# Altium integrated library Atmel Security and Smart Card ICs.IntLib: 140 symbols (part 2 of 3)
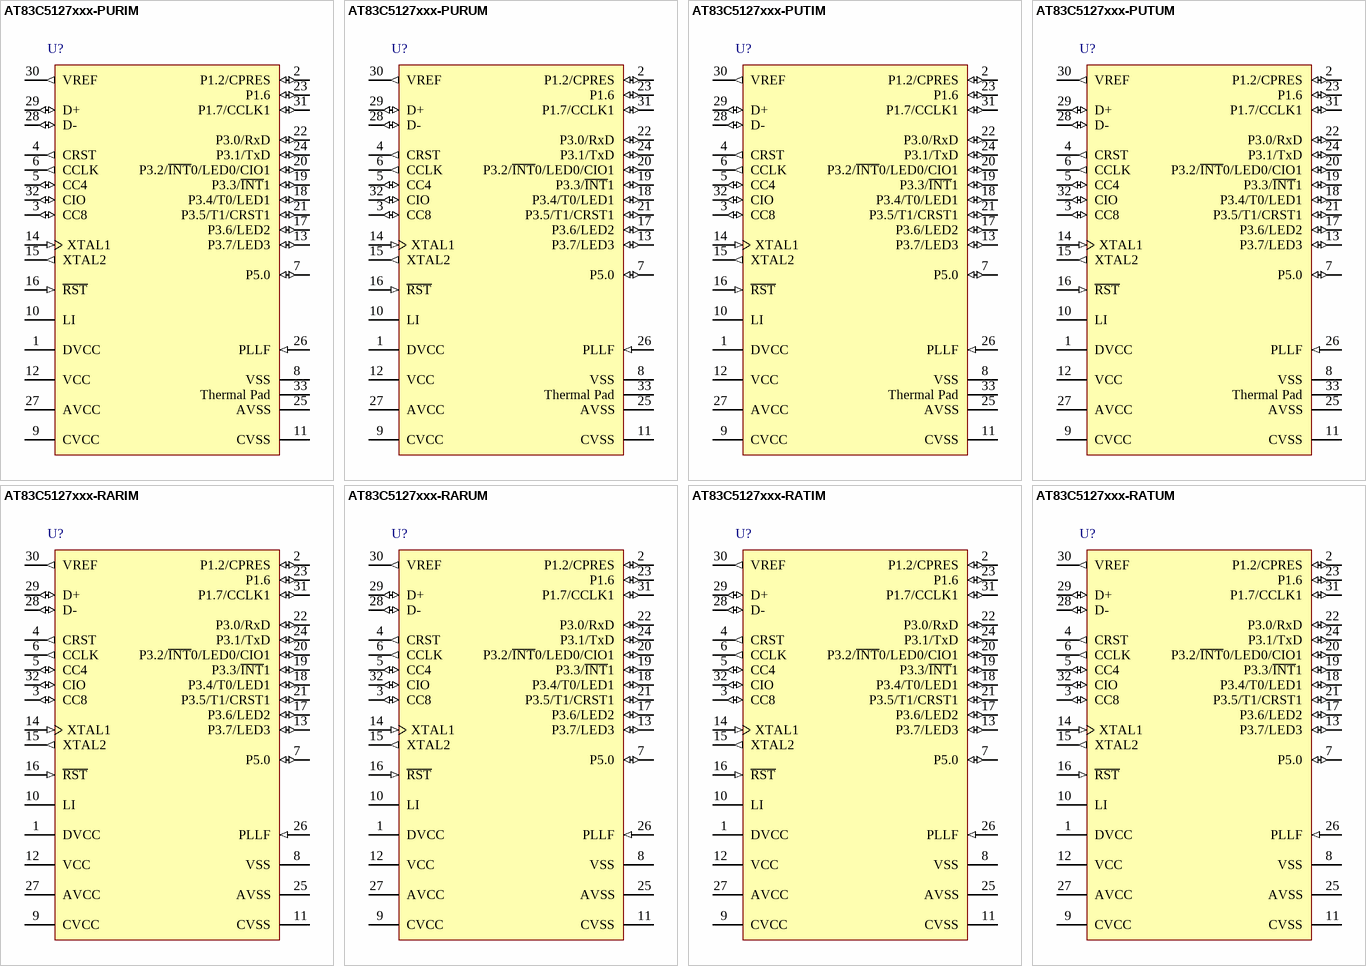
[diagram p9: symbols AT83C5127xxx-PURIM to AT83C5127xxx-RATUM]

## AT83C5127xxx-RARIM
designator U?
C51 Microcontroller with USB and Smart Card Reader Interfaces, Industrial, 32-Pin QFP Pkg, Tape and Reel
footprint LQFP32_N (Thin QFP, 32-Leads, Body 7x7mm, Pitch 0.8mm, IPC Medium Density)
footprint LQFP32_L (Thin QFP, 32-Leads, Body 7x7mm, Pitch 0.8mm, IPC High Density)
footprint LQFP32_M (Thin QFP, 32-Leads, Body 7x7mm, Pitch 0.8mm, IPC Low Density)
pins: 1 DVCC (power), 2 P1.2/CPRES (io), 3 CC8 (io), 4 CRST (out), 5 CC4 (io), 6 CCLK (out), 7 P5.0 (io), 8 VSS (power), 9 CVCC (power), 10 LI (power), 11 CVSS (power), 12 VCC (power), 13 P3.7/LED3 (io), 14 XTAL1 (in), 15 XTAL2 (out), 16 ~{RST} (in), 17 P3.6/LED2 (io), 18 P3.4/T0/LED1 (io), 19 P3.3/~{INT}1 (io), 20 P3.2/~{INT}0/LED0/CIO1 (io), 21 P3.5/T1/CRST1 (io), 22 P3.0/RxD (io), 23 P1.6 (io), 24 P3.1/TxD (io), 25 AVSS (power), 26 PLLF (in), 27 AVCC (power), 28 D- (io), 29 D+ (io), 30 VREF (out), 31 P1.7/CCLK1 (io), 32 CIO (io)

## AT83C5127xxx-RARUM
designator U?
C51 Microcontroller with USB and Smart Card Reader Interfaces, Industrial, 32-Pin QFP Pkg, Tape and Reel, Pb-Free
footprint LQFP32_N (Thin QFP, 32-Leads, Body 7x7mm, Pitch 0.8mm, IPC Medium Density)
footprint LQFP32_L (Thin QFP, 32-Leads, Body 7x7mm, Pitch 0.8mm, IPC High Density)
footprint LQFP32_M (Thin QFP, 32-Leads, Body 7x7mm, Pitch 0.8mm, IPC Low Density)
pins: 1 DVCC (power), 2 P1.2/CPRES (io), 3 CC8 (io), 4 CRST (out), 5 CC4 (io), 6 CCLK (out), 7 P5.0 (io), 8 VSS (power), 9 CVCC (power), 10 LI (power), 11 CVSS (power), 12 VCC (power), 13 P3.7/LED3 (io), 14 XTAL1 (in), 15 XTAL2 (out), 16 ~{RST} (in), 17 P3.6/LED2 (io), 18 P3.4/T0/LED1 (io), 19 P3.3/~{INT}1 (io), 20 P3.2/~{INT}0/LED0/CIO1 (io), 21 P3.5/T1/CRST1 (io), 22 P3.0/RxD (io), 23 P1.6 (io), 24 P3.1/TxD (io), 25 AVSS (power), 26 PLLF (in), 27 AVCC (power), 28 D- (io), 29 D+ (io), 30 VREF (out), 31 P1.7/CCLK1 (io), 32 CIO (io)

## AT83C5127xxx-RATIM
designator U?
C51 Microcontroller with USB and Smart Card Reader Interfaces, Industrial, 32-Pin QFP Pkg, Tray
footprint LQFP32_N (Thin QFP, 32-Leads, Body 7x7mm, Pitch 0.8mm, IPC Medium Density)
footprint LQFP32_L (Thin QFP, 32-Leads, Body 7x7mm, Pitch 0.8mm, IPC High Density)
footprint LQFP32_M (Thin QFP, 32-Leads, Body 7x7mm, Pitch 0.8mm, IPC Low Density)
pins: 1 DVCC (power), 2 P1.2/CPRES (io), 3 CC8 (io), 4 CRST (out), 5 CC4 (io), 6 CCLK (out), 7 P5.0 (io), 8 VSS (power), 9 CVCC (power), 10 LI (power), 11 CVSS (power), 12 VCC (power), 13 P3.7/LED3 (io), 14 XTAL1 (in), 15 XTAL2 (out), 16 ~{RST} (in), 17 P3.6/LED2 (io), 18 P3.4/T0/LED1 (io), 19 P3.3/~{INT}1 (io), 20 P3.2/~{INT}0/LED0/CIO1 (io), 21 P3.5/T1/CRST1 (io), 22 P3.0/RxD (io), 23 P1.6 (io), 24 P3.1/TxD (io), 25 AVSS (power), 26 PLLF (in), 27 AVCC (power), 28 D- (io), 29 D+ (io), 30 VREF (out), 31 P1.7/CCLK1 (io), 32 CIO (io)

## AT83C5127xxx-RATUM
designator U?
C51 Microcontroller with USB and Smart Card Reader Interfaces, Industrial, 32-Pin QFP Pkg, Tray, Pb-Free
footprint LQFP32_N (Thin QFP, 32-Leads, Body 7x7mm, Pitch 0.8mm, IPC Medium Density)
footprint LQFP32_L (Thin QFP, 32-Leads, Body 7x7mm, Pitch 0.8mm, IPC High Density)
footprint LQFP32_M (Thin QFP, 32-Leads, Body 7x7mm, Pitch 0.8mm, IPC Low Density)
pins: 1 DVCC (power), 2 P1.2/CPRES (io), 3 CC8 (io), 4 CRST (out), 5 CC4 (io), 6 CCLK (out), 7 P5.0 (io), 8 VSS (power), 9 CVCC (power), 10 LI (power), 11 CVSS (power), 12 VCC (power), 13 P3.7/LED3 (io), 14 XTAL1 (in), 15 XTAL2 (out), 16 ~{RST} (in), 17 P3.6/LED2 (io), 18 P3.4/T0/LED1 (io), 19 P3.3/~{INT}1 (io), 20 P3.2/~{INT}0/LED0/CIO1 (io), 21 P3.5/T1/CRST1 (io), 22 P3.0/RxD (io), 23 P1.6 (io), 24 P3.1/TxD (io), 25 AVSS (power), 26 PLLF (in), 27 AVCC (power), 28 D- (io), 29 D+ (io), 30 VREF (out), 31 P1.7/CCLK1 (io), 32 CIO (io)

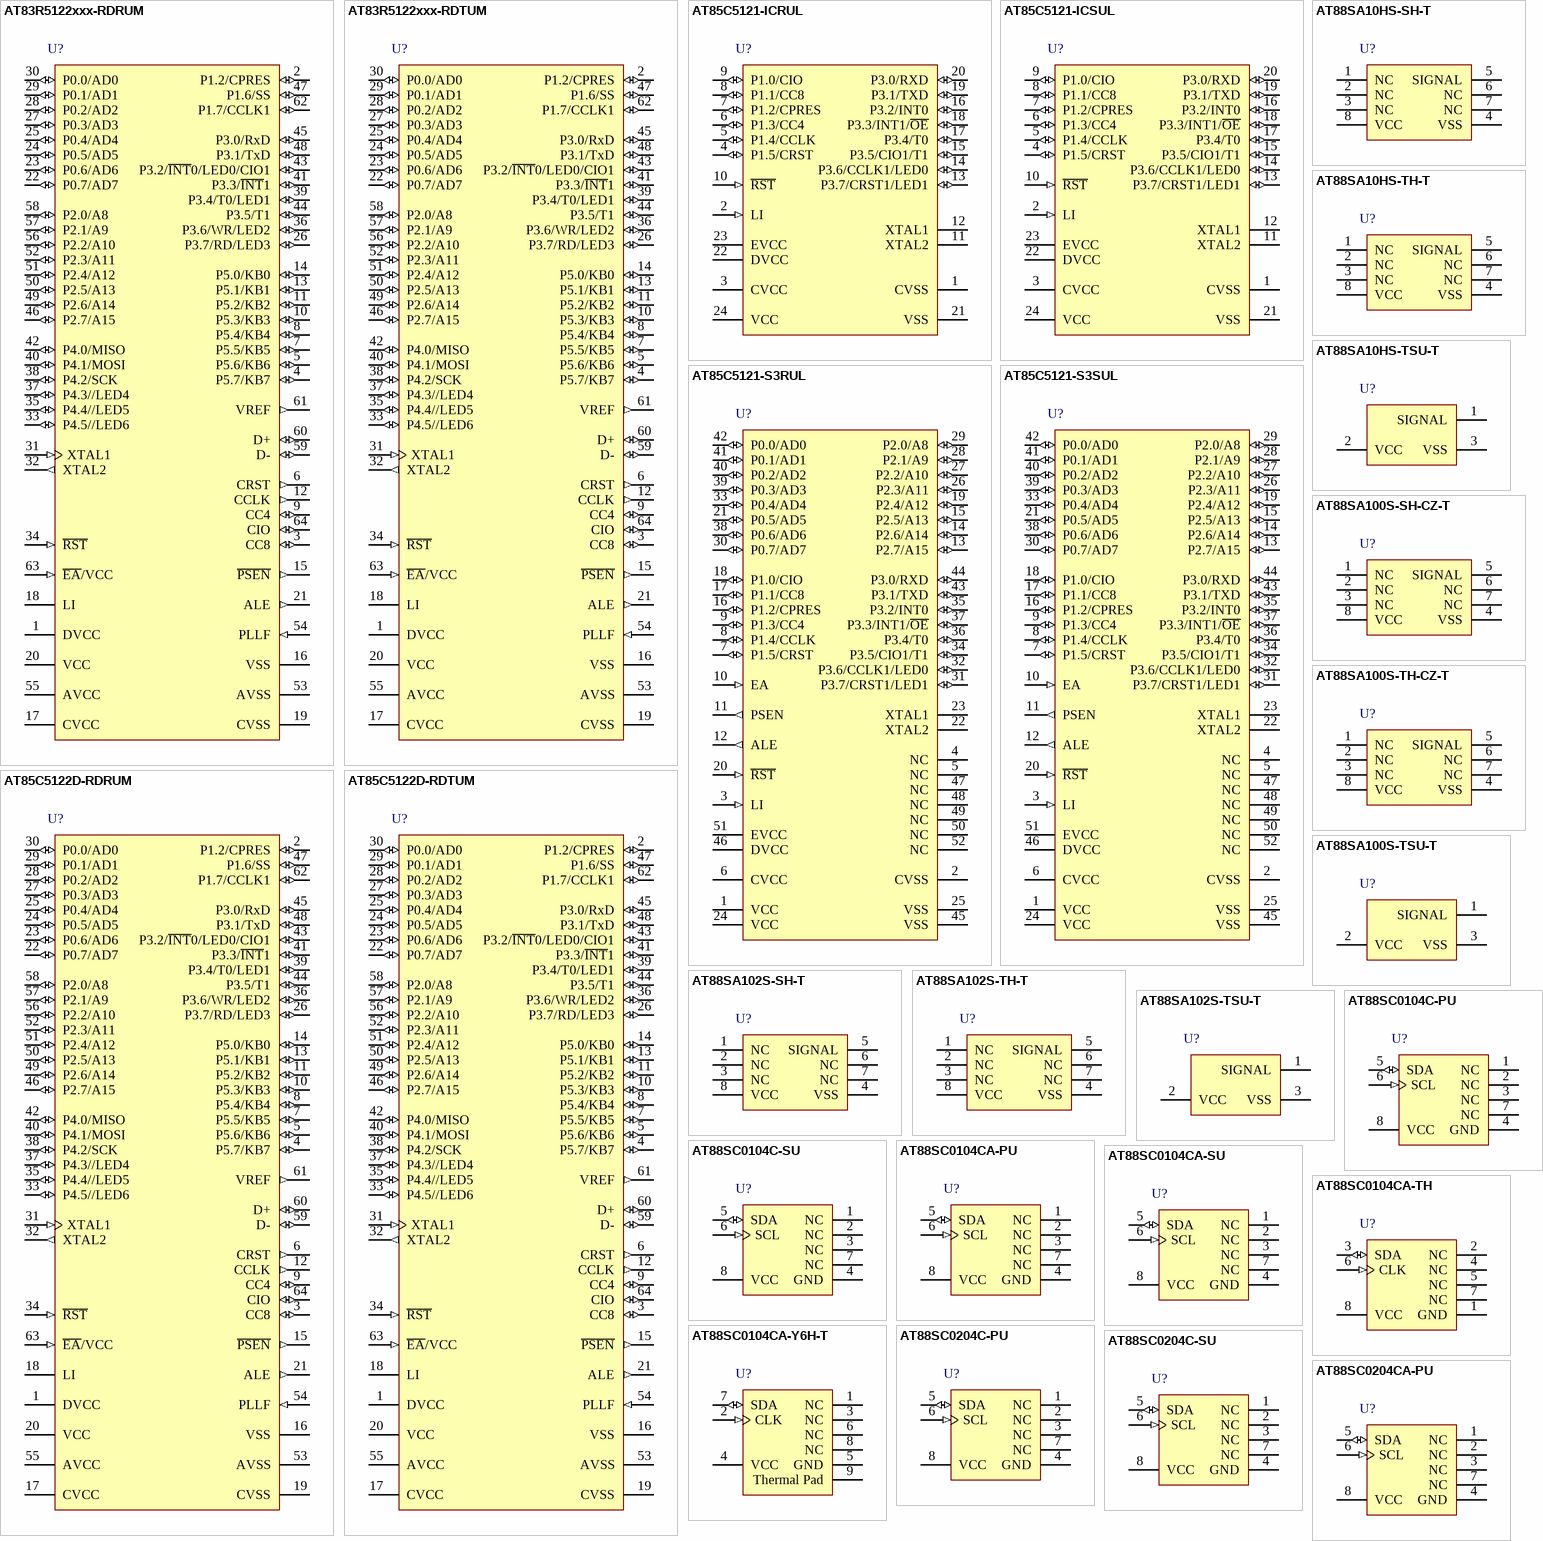
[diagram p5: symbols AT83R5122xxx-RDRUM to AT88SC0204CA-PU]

## AT83R5122xxx-RDRUM
designator U?
C51 Microcontroller with USB and Smart Card Reader Interfaces, 32K ROM, Industrial, 64-Pin QFP Pkg, Tape and Reel
footprint LQFP64_N (Thin QFP, 64-Leads, Body 10x10mm, Pitch 0.5mm, IPC Medium Density)
footprint LQFP64_L (Thin QFP, 64-Leads, Body 10x10mm, Pitch 0.5mm, IPC High Density)
footprint LQFP64_M (Thin QFP, 64-Leads, Body 10x10mm, Pitch 0.5mm, IPC Low Density)
pins: 1 DVCC (power), 2 P1.2/CPRES (io), 3 CC8 (io), 4 P5.7/KB7 (io), 5 P5.6/KB6 (io), 6 CRST (out), 7 P5.5/KB5 (io), 8 P5.4/KB4 (io), 9 CC4 (io), 10 P5.3/KB3 (io), 11 P5.2/KB2 (io), 12 CCLK (out), 13 P5.1/KB1 (io), 14 P5.0/KB0 (io), 15 ~{PSEN} (out), 16 VSS (power), 17 CVCC (power), 18 LI (power), 19 CVSS (power), 20 VCC (power), 21 ALE (out), 22 P0.7/AD7 (io), 23 P0.6/AD6 (io), 24 P0.5/AD5 (io), 25 P0.4/AD4 (io), 26 P3.7/RD/LED3 (io), 27 P0.3/AD3 (io), 28 P0.2/AD2 (io), 29 P0.1/AD1 (io), 30 P0.0/AD0 (io), 31 XTAL1 (in), 32 XTAL2 (out), 33 P4.5//LED6 (io), 34 ~{RST} (in), 35 P4.4//LED5 (io), 36 P3.6/WR/LED2 (io), 37 P4.3//LED4 (io), 38 P4.2/SCK (io), 39 P3.4/T0/LED1 (io), 40 P4.1/MOSI (io), 41 P3.3/~{INT}1 (io), 42 P4.0/MISO (io), 43 P3.2/~{INT}0/LED0/CIO1 (io), 44 P3.5/T1 (io), 45 P3.0/RxD (io), 46 P2.7/A15 (io), 47 P1.6/SS (io), 48 P3.1/TxD (io), 49 P2.6/A14 (io), 50 P2.5/A13 (io), 51 P2.4/A12 (io), 52 P2.3/A11 (io), 53 AVSS (power), 54 PLLF (in), 55 AVCC (power), 56 P2.2/A10 (io), 57 P2.1/A9 (io), 58 P2.0/A8 (io), 59 D- (io), 60 D+ (io), 61 VREF (out), 62 P1.7/CCLK1 (io), 63 ~{EA}/VCC (in), 64 CIO (io)

## AT83R5122xxx-RDTUM
designator U?
C51 Microcontroller with USB and Smart Card Reader Interfaces, 32K ROM, Industrial, 64-Pin QFP Pkg, Tray
footprint LQFP64_N (Thin QFP, 64-Leads, Body 10x10mm, Pitch 0.5mm, IPC Medium Density)
footprint LQFP64_L (Thin QFP, 64-Leads, Body 10x10mm, Pitch 0.5mm, IPC High Density)
footprint LQFP64_M (Thin QFP, 64-Leads, Body 10x10mm, Pitch 0.5mm, IPC Low Density)
pins: 1 DVCC (power), 2 P1.2/CPRES (io), 3 CC8 (io), 4 P5.7/KB7 (io), 5 P5.6/KB6 (io), 6 CRST (out), 7 P5.5/KB5 (io), 8 P5.4/KB4 (io), 9 CC4 (io), 10 P5.3/KB3 (io), 11 P5.2/KB2 (io), 12 CCLK (out), 13 P5.1/KB1 (io), 14 P5.0/KB0 (io), 15 ~{PSEN} (out), 16 VSS (power), 17 CVCC (power), 18 LI (power), 19 CVSS (power), 20 VCC (power), 21 ALE (out), 22 P0.7/AD7 (io), 23 P0.6/AD6 (io), 24 P0.5/AD5 (io), 25 P0.4/AD4 (io), 26 P3.7/RD/LED3 (io), 27 P0.3/AD3 (io), 28 P0.2/AD2 (io), 29 P0.1/AD1 (io), 30 P0.0/AD0 (io), 31 XTAL1 (in), 32 XTAL2 (out), 33 P4.5//LED6 (io), 34 ~{RST} (in), 35 P4.4//LED5 (io), 36 P3.6/WR/LED2 (io), 37 P4.3//LED4 (io), 38 P4.2/SCK (io), 39 P3.4/T0/LED1 (io), 40 P4.1/MOSI (io), 41 P3.3/~{INT}1 (io), 42 P4.0/MISO (io), 43 P3.2/~{INT}0/LED0/CIO1 (io), 44 P3.5/T1 (io), 45 P3.0/RxD (io), 46 P2.7/A15 (io), 47 P1.6/SS (io), 48 P3.1/TxD (io), 49 P2.6/A14 (io), 50 P2.5/A13 (io), 51 P2.4/A12 (io), 52 P2.3/A11 (io), 53 AVSS (power), 54 PLLF (in), 55 AVCC (power), 56 P2.2/A10 (io), 57 P2.1/A9 (io), 58 P2.0/A8 (io), 59 D- (io), 60 D+ (io), 61 VREF (out), 62 P1.7/CCLK1 (io), 63 ~{EA}/VCC (in), 64 CIO (io)

## AT85C5121-ICRUL
designator U?
8-bit Microcontroller with Multiprotocol Smart Card Interface, Industrial, 24-Pin SOIC Pkg, Tape and Reel, Pb-Free
footprint SSOP24_N (SOP, 24-Leads, Body 8.2x5.3mm, Pitch 0.65mm, IPC Medium Density)
footprint SSOP24_L (SOP, 24-Leads, Body 8.2x5.3mm, Pitch 0.65mm, IPC High Density)
footprint SSOP24_M (SOP, 24-Leads, Body 8.2x5.3mm, Pitch 0.65mm, IPC Low Density)
pins: 1 CVSS (power), 2 LI (in), 3 CVCC (power), 4 P1.5/CRST (io), 5 P1.4/CCLK (io), 6 P1.3/CC4 (io), 7 P1.2/CPRES (io), 8 P1.1/CC8 (io), 9 P1.0/CIO (io), 10 ~{RST} (in), 11 XTAL2, 12 XTAL1, 13 P3.7/CRST1/LED1 (io), 14 P3.6/CCLK1/LED0 (io), 15 P3.5/CIO1/T1 (io), 16 P3.2/INT0 (io), 17 P3.4/T0 (io), 18 P3.3/INT1/~{OE} (io), 19 P3.1/TXD (io), 20 P3.0/RXD (io), 21 VSS (power), 22 DVCC (power), 23 EVCC (power), 24 VCC (power)

## AT85C5121-ICSUL
designator U?
8-bit Microcontroller with Multiprotocol Smart Card Interface, Industrial, 24-Pin SOIC Pkg, Stick, Pb-Free
footprint SSOP24_N (SOP, 24-Leads, Body 8.2x5.3mm, Pitch 0.65mm, IPC Medium Density)
footprint SSOP24_L (SOP, 24-Leads, Body 8.2x5.3mm, Pitch 0.65mm, IPC High Density)
footprint SSOP24_M (SOP, 24-Leads, Body 8.2x5.3mm, Pitch 0.65mm, IPC Low Density)
pins: 1 CVSS (power), 2 LI (in), 3 CVCC (power), 4 P1.5/CRST (io), 5 P1.4/CCLK (io), 6 P1.3/CC4 (io), 7 P1.2/CPRES (io), 8 P1.1/CC8 (io), 9 P1.0/CIO (io), 10 ~{RST} (in), 11 XTAL2, 12 XTAL1, 13 P3.7/CRST1/LED1 (io), 14 P3.6/CCLK1/LED0 (io), 15 P3.5/CIO1/T1 (io), 16 P3.2/INT0 (io), 17 P3.4/T0 (io), 18 P3.3/INT1/~{OE} (io), 19 P3.1/TXD (io), 20 P3.0/RXD (io), 21 VSS (power), 22 DVCC (power), 23 EVCC (power), 24 VCC (power)

## AT85C5121-S3RUL
designator U?
8-bit Microcontroller with Multiprotocol Smart Card Interface, Industrial, 52-Pin LCC Pkg, Tape and Reel, Pb-Free
footprint PLCC52_N (Leaded Chip Carrier, 52-Leads, Body 19x19mm, Pitch 1.27mm, IPC Medium Density)
footprint PLCC52_L (Leaded Chip Carrier, 52-Leads, Body 19x19mm, Pitch 1.27mm, IPC High Density)
footprint PLCC52_M (Leaded Chip Carrier, 52-Leads, Body 19x19mm, Pitch 1.27mm, IPC Low Density)
pins: 1 VCC (power), 2 CVSS (power), 3 LI (in), 4 NC, 5 NC, 6 CVCC (power), 7 P1.5/CRST (io), 8 P1.4/CCLK (io), 9 P1.3/CC4 (io), 10 EA (in), 11 PSEN (out), 12 ALE (out), 13 P2.7/A15 (io), 14 P2.6/A14 (io), 15 P2.5/A13 (io), 16 P1.2/CPRES (io), 17 P1.1/CC8 (io), 18 P1.0/CIO (io), 19 P2.4/A12 (io), 20 ~{RST} (in), 21 P0.5/AD5 (io), 22 XTAL2, 23 XTAL1, 24 VCC (power), 25 VSS (power), 26 P2.3/A11 (io), 27 P2.2/A10 (io), 28 P2.1/A9 (io), 29 P2.0/A8 (io), 30 P0.7/AD7 (io), 31 P3.7/CRST1/LED1 (io), 32 P3.6/CCLK1/LED0 (io), 33 P0.4/AD4 (io), 34 P3.5/CIO1/T1 (io), 35 P3.2/INT0 (io), 36 P3.4/T0 (io), 37 P3.3/INT1/~{OE} (io), 38 P0.6/AD6 (io), 39 P0.3/AD3 (io), 40 P0.2/AD2 (io), 41 P0.1/AD1 (io), 42 P0.0/AD0 (io), 43 P3.1/TXD (io), 44 P3.0/RXD (io), 45 VSS (power), 46 DVCC (power), 47 NC, 48 NC, 49 NC, 50 NC, 51 EVCC (power), 52 NC

## AT85C5121-S3SUL
designator U?
8-bit Microcontroller with Multiprotocol Smart Card Interface, Industrial, 52-Pin LCC Pkg, Stick, Pb-Free
footprint PLCC52_N (Leaded Chip Carrier, 52-Leads, Body 19x19mm, Pitch 1.27mm, IPC Medium Density)
footprint PLCC52_L (Leaded Chip Carrier, 52-Leads, Body 19x19mm, Pitch 1.27mm, IPC High Density)
footprint PLCC52_M (Leaded Chip Carrier, 52-Leads, Body 19x19mm, Pitch 1.27mm, IPC Low Density)
pins: 1 VCC (power), 2 CVSS (power), 3 LI (in), 4 NC, 5 NC, 6 CVCC (power), 7 P1.5/CRST (io), 8 P1.4/CCLK (io), 9 P1.3/CC4 (io), 10 EA (in), 11 PSEN (out), 12 ALE (out), 13 P2.7/A15 (io), 14 P2.6/A14 (io), 15 P2.5/A13 (io), 16 P1.2/CPRES (io), 17 P1.1/CC8 (io), 18 P1.0/CIO (io), 19 P2.4/A12 (io), 20 ~{RST} (in), 21 P0.5/AD5 (io), 22 XTAL2, 23 XTAL1, 24 VCC (power), 25 VSS (power), 26 P2.3/A11 (io), 27 P2.2/A10 (io), 28 P2.1/A9 (io), 29 P2.0/A8 (io), 30 P0.7/AD7 (io), 31 P3.7/CRST1/LED1 (io), 32 P3.6/CCLK1/LED0 (io), 33 P0.4/AD4 (io), 34 P3.5/CIO1/T1 (io), 35 P3.2/INT0 (io), 36 P3.4/T0 (io), 37 P3.3/INT1/~{OE} (io), 38 P0.6/AD6 (io), 39 P0.3/AD3 (io), 40 P0.2/AD2 (io), 41 P0.1/AD1 (io), 42 P0.0/AD0 (io), 43 P3.1/TXD (io), 44 P3.0/RXD (io), 45 VSS (power), 46 DVCC (power), 47 NC, 48 NC, 49 NC, 50 NC, 51 EVCC (power), 52 NC

## AT85C5122D-RDRUM
designator U?
C51 Microcontroller with USB and Smart Card Reader Interfaces, 32K CRAM, Industrial, 64-Pin QFP Pkg, Tape and Reel
footprint LQFP64_N (Thin QFP, 64-Leads, Body 10x10mm, Pitch 0.5mm, IPC Medium Density)
footprint LQFP64_L (Thin QFP, 64-Leads, Body 10x10mm, Pitch 0.5mm, IPC High Density)
footprint LQFP64_M (Thin QFP, 64-Leads, Body 10x10mm, Pitch 0.5mm, IPC Low Density)
pins: 1 DVCC (power), 2 P1.2/CPRES (io), 3 CC8 (io), 4 P5.7/KB7 (io), 5 P5.6/KB6 (io), 6 CRST (out), 7 P5.5/KB5 (io), 8 P5.4/KB4 (io), 9 CC4 (io), 10 P5.3/KB3 (io), 11 P5.2/KB2 (io), 12 CCLK (out), 13 P5.1/KB1 (io), 14 P5.0/KB0 (io), 15 ~{PSEN} (out), 16 VSS (power), 17 CVCC (power), 18 LI (power), 19 CVSS (power), 20 VCC (power), 21 ALE (out), 22 P0.7/AD7 (io), 23 P0.6/AD6 (io), 24 P0.5/AD5 (io), 25 P0.4/AD4 (io), 26 P3.7/RD/LED3 (io), 27 P0.3/AD3 (io), 28 P0.2/AD2 (io), 29 P0.1/AD1 (io), 30 P0.0/AD0 (io), 31 XTAL1 (in), 32 XTAL2 (out), 33 P4.5//LED6 (io), 34 ~{RST} (in), 35 P4.4//LED5 (io), 36 P3.6/WR/LED2 (io), 37 P4.3//LED4 (io), 38 P4.2/SCK (io), 39 P3.4/T0/LED1 (io), 40 P4.1/MOSI (io), 41 P3.3/~{INT}1 (io), 42 P4.0/MISO (io), 43 P3.2/~{INT}0/LED0/CIO1 (io), 44 P3.5/T1 (io), 45 P3.0/RxD (io), 46 P2.7/A15 (io), 47 P1.6/SS (io), 48 P3.1/TxD (io), 49 P2.6/A14 (io), 50 P2.5/A13 (io), 51 P2.4/A12 (io), 52 P2.3/A11 (io), 53 AVSS (power), 54 PLLF (in), 55 AVCC (power), 56 P2.2/A10 (io), 57 P2.1/A9 (io), 58 P2.0/A8 (io), 59 D- (io), 60 D+ (io), 61 VREF (out), 62 P1.7/CCLK1 (io), 63 ~{EA}/VCC (in), 64 CIO (io)

## AT85C5122D-RDTUM
designator U?
C51 Microcontroller with USB and Smart Card Reader Interfaces, 32K CRAM, Industrial, 64-Pin QFP Pkg, Tray
footprint LQFP64_N (Thin QFP, 64-Leads, Body 10x10mm, Pitch 0.5mm, IPC Medium Density)
footprint LQFP64_L (Thin QFP, 64-Leads, Body 10x10mm, Pitch 0.5mm, IPC High Density)
footprint LQFP64_M (Thin QFP, 64-Leads, Body 10x10mm, Pitch 0.5mm, IPC Low Density)
pins: 1 DVCC (power), 2 P1.2/CPRES (io), 3 CC8 (io), 4 P5.7/KB7 (io), 5 P5.6/KB6 (io), 6 CRST (out), 7 P5.5/KB5 (io), 8 P5.4/KB4 (io), 9 CC4 (io), 10 P5.3/KB3 (io), 11 P5.2/KB2 (io), 12 CCLK (out), 13 P5.1/KB1 (io), 14 P5.0/KB0 (io), 15 ~{PSEN} (out), 16 VSS (power), 17 CVCC (power), 18 LI (power), 19 CVSS (power), 20 VCC (power), 21 ALE (out), 22 P0.7/AD7 (io), 23 P0.6/AD6 (io), 24 P0.5/AD5 (io), 25 P0.4/AD4 (io), 26 P3.7/RD/LED3 (io), 27 P0.3/AD3 (io), 28 P0.2/AD2 (io), 29 P0.1/AD1 (io), 30 P0.0/AD0 (io), 31 XTAL1 (in), 32 XTAL2 (out), 33 P4.5//LED6 (io), 34 ~{RST} (in), 35 P4.4//LED5 (io), 36 P3.6/WR/LED2 (io), 37 P4.3//LED4 (io), 38 P4.2/SCK (io), 39 P3.4/T0/LED1 (io), 40 P4.1/MOSI (io), 41 P3.3/~{INT}1 (io), 42 P4.0/MISO (io), 43 P3.2/~{INT}0/LED0/CIO1 (io), 44 P3.5/T1 (io), 45 P3.0/RxD (io), 46 P2.7/A15 (io), 47 P1.6/SS (io), 48 P3.1/TxD (io), 49 P2.6/A14 (io), 50 P2.5/A13 (io), 51 P2.4/A12 (io), 52 P2.3/A11 (io), 53 AVSS (power), 54 PLLF (in), 55 AVCC (power), 56 P2.2/A10 (io), 57 P2.1/A9 (io), 58 P2.0/A8 (io), 59 D- (io), 60 D+ (io), 61 VREF (out), 62 P1.7/CCLK1 (io), 63 ~{EA}/VCC (in), 64 CIO (io)

## AT88SA10HS-SH-T
designator U?
CryptoAuthentication™ Host Security Chip, Industrial (-40 to 85 degC), 8-Pin SOIC, Tape and Reel, Pb-Free
footprint 8S1_N (SOIC, 8-Leads, Body 4.9x3.9mm, Pitch 1.27mm, IPC Medium Density)
footprint 8S1_L (SOIC, 8-Leads, Body 4.9x3.9mm, Pitch 1.27mm, IPC High Density)
footprint 8S1_M (SOIC, 8-Leads, Body 4.9x3.9mm, Pitch 1.27mm, IPC Low Density)
pins: 1 NC, 2 NC, 3 NC, 4 VSS (power), 5 SIGNAL (oc), 6 NC, 7 NC, 8 VCC (power)

## AT88SA10HS-TH-T
designator U?
CryptoAuthentication™ Host Security Chip, Industrial (-40 to 85 degC), 8-Pin TSOP, Tape and Reel, Pb-Free
footprint 8A2_N (TSOP, 8-Leads, Body 3x4.4mm, Pitch 0.65mm, IPC Medium Density)
footprint 8A2_L (TSOP, 8-Leads, Body 3x4.4mm, Pitch 0.65mm, IPC High Density)
footprint 8A2_M (TSOP, 8-Leads, Body 3x4.4mm, Pitch 0.65mm, IPC Low Density)
pins: 1 NC, 2 NC, 3 NC, 4 VSS (power), 5 SIGNAL (oc), 6 NC, 7 NC, 8 VCC (power)

## AT88SA10HS-TSU-T
designator U?
CryptoAuthentication™ Host Security Chip, Industrial (-40 to 85 degC), 3-Pin SOT, Tape and Reel, Pb-Free
footprint 3TS1_N (SOT23, 3-Leads, Body 2.9x1.3mm, Pitch 0.95mm, Lead Span 2.4mm, IPC Medium Density)
footprint 3TS1_L (SOT23, 3-Leads, Body 2.9x1.3mm, Pitch 0.95mm, Lead Span 2.4mm, IPC High Density)
footprint 3TS1_M (SOT23, 3-Leads, Body 2.9x1.3mm, Pitch 0.95mm, Lead Span 2.4mm, IPC Low Density)
pins: 1 SIGNAL (oc), 2 VCC (power), 3 VSS (power)

## AT88SA100S-SH-CZ-T
designator U?
CryptoAuthentication™ Battery Authentication Chip, Industrial (-40 to 85 degC), 8-Pin SOIC, Tape and Reel
footprint 8S1_N (SOIC, 8-Leads, Body 4.9x3.9mm, Pitch 1.27mm, IPC Medium Density)
footprint 8S1_L (SOIC, 8-Leads, Body 4.9x3.9mm, Pitch 1.27mm, IPC High Density)
footprint 8S1_M (SOIC, 8-Leads, Body 4.9x3.9mm, Pitch 1.27mm, IPC Low Density)
pins: 1 NC, 2 NC, 3 NC, 4 VSS (power), 5 SIGNAL (oc), 6 NC, 7 NC, 8 VCC (power)

## AT88SA100S-TH-CZ-T
designator U?
CryptoAuthentication™ Battery Authentication Chip, Industrial (-40 to 85 degC), 8-Pin TSSOP, Tape and Reel
footprint 8A2_N (TSOP, 8-Leads, Body 3x4.4mm, Pitch 0.65mm, IPC Medium Density)
footprint 8A2_L (TSOP, 8-Leads, Body 3x4.4mm, Pitch 0.65mm, IPC High Density)
footprint 8A2_M (TSOP, 8-Leads, Body 3x4.4mm, Pitch 0.65mm, IPC Low Density)
pins: 1 NC, 2 NC, 3 NC, 4 VSS (power), 5 SIGNAL (oc), 6 NC, 7 NC, 8 VCC (power)

## AT88SA100S-TSU-T
designator U?
CryptoAuthentication™ Battery Authentication Chip, Industrial (-40 to 85 degC), 3-Pin SOT, Tape and Reel
footprint 3TS1_N (SOT23, 3-Leads, Body 2.9x1.3mm, Pitch 0.95mm, Lead Span 2.4mm, IPC Medium Density)
footprint 3TS1_L (SOT23, 3-Leads, Body 2.9x1.3mm, Pitch 0.95mm, Lead Span 2.4mm, IPC High Density)
footprint 3TS1_M (SOT23, 3-Leads, Body 2.9x1.3mm, Pitch 0.95mm, Lead Span 2.4mm, IPC Low Density)
pins: 1 SIGNAL (oc), 2 VCC (power), 3 VSS (power)

## AT88SA102S-SH-T
designator U?
CryptoAuthentication™ Product Authentication Chip, Industrial (-40 to 85 degC), 8-Pin SOIC, Tape and Reel, Pb-Free
footprint 8S1_N (SOIC, 8-Leads, Body 4.9x3.9mm, Pitch 1.27mm, IPC Medium Density)
footprint 8S1_L (SOIC, 8-Leads, Body 4.9x3.9mm, Pitch 1.27mm, IPC High Density)
footprint 8S1_M (SOIC, 8-Leads, Body 4.9x3.9mm, Pitch 1.27mm, IPC Low Density)
pins: 1 NC, 2 NC, 3 NC, 4 VSS (power), 5 SIGNAL (oc), 6 NC, 7 NC, 8 VCC (power)

## AT88SA102S-TH-T
designator U?
CryptoAuthentication™ Product Authentication Chip, Industrial (-40 to 85 degC), 8-Pin TSOP, Tape and Reel, Pb-Free
footprint 8A2_N (TSOP, 8-Leads, Body 3x4.4mm, Pitch 0.65mm, IPC Medium Density)
footprint 8A2_L (TSOP, 8-Leads, Body 3x4.4mm, Pitch 0.65mm, IPC High Density)
footprint 8A2_M (TSOP, 8-Leads, Body 3x4.4mm, Pitch 0.65mm, IPC Low Density)
pins: 1 NC, 2 NC, 3 NC, 4 VSS (power), 5 SIGNAL (oc), 6 NC, 7 NC, 8 VCC (power)

## AT88SA102S-TSU-T
designator U?
CryptoAuthentication™ Product Authentication Chip, Industrial (-40 to 85 degC), 3-Pin SOT, Tape and Reel, Pb-Free
footprint 3TS1_N (SOT23, 3-Leads, Body 2.9x1.3mm, Pitch 0.95mm, Lead Span 2.4mm, IPC Medium Density)
footprint 3TS1_L (SOT23, 3-Leads, Body 2.9x1.3mm, Pitch 0.95mm, Lead Span 2.4mm, IPC High Density)
footprint 3TS1_M (SOT23, 3-Leads, Body 2.9x1.3mm, Pitch 0.95mm, Lead Span 2.4mm, IPC Low Density)
pins: 1 SIGNAL (oc), 2 VCC (power), 3 VSS (power)

## AT88SC0104C-PU
designator U?
AT88SC0104C CryptoMemory®: 1-Kbit User Memory with Authentication and Encryption, Industrial (-40 to 85 degC), 8-Pin PDIP Pkg, Pb-Free
footprint 8P3 (DIP, 8-Leads, Row Spacing 7.62mm, Pitch 2.54mm, Body 9.59x6.61mm)
pins: 1 NC, 2 NC, 3 NC, 4 GND (power), 5 SDA (io), 6 SCL (in), 7 NC, 8 VCC (power)

## AT88SC0104C-SU
designator U?
AT88SC0104C CryptoMemory®: 1-Kbit User Memory with Authentication and Encryption, Industrial (-40 to 85 degC), 8-Pin SOIC Pkg, Pb-Free
footprint 8S1_N (SOIC, 8-Leads, Body 4.9x3.9mm, Pitch 1.27mm, IPC Medium Density)
footprint 8S1_L (SOIC, 8-Leads, Body 4.9x3.9mm, Pitch 1.27mm, IPC High Density)
footprint 8S1_M (SOIC, 8-Leads, Body 4.9x3.9mm, Pitch 1.27mm, IPC Low Density)
pins: 1 NC, 2 NC, 3 NC, 4 GND (power), 5 SDA (io), 6 SCL (in), 7 NC, 8 VCC (power)

## AT88SC0104CA-PU
designator U?
AT88SC0104CA CryptoMemory®: 1-Kbit User Memory with Authentication and Encryption, Industrial (-40 to 85 degC), 8-Pin PDIP Pkg, Pb-Free
footprint 8P3 (DIP, 8-Leads, Row Spacing 7.62mm, Pitch 2.54mm, Body 9.59x6.61mm)
pins: 1 NC, 2 NC, 3 NC, 4 GND (power), 5 SDA (io), 6 SCL (in), 7 NC, 8 VCC (power)

## AT88SC0104CA-SU
designator U?
AT88SC0104CA CryptoMemory®: 1-Kbit User Memory with Authentication and Encryption, Industrial (-40 to 85 degC), 8-Pin SOIC Pkg, Pb-Free
footprint 8S1_N (SOIC, 8-Leads, Body 4.9x3.9mm, Pitch 1.27mm, IPC Medium Density)
footprint 8S1_L (SOIC, 8-Leads, Body 4.9x3.9mm, Pitch 1.27mm, IPC High Density)
footprint 8S1_M (SOIC, 8-Leads, Body 4.9x3.9mm, Pitch 1.27mm, IPC Low Density)
pins: 1 NC, 2 NC, 3 NC, 4 GND (power), 5 SDA (io), 6 SCL (in), 7 NC, 8 VCC (power)

## AT88SC0104CA-TH
designator U?
AT88SC0104CA CryptoMemory®: 1-Kbit User Memory with Authentication and Encryption, Industrial (-40 to 85 degC), 8-Pin TSSOP Pkg, Pb-Free
footprint 8A2_N (TSOP, 8-Leads, Body 3x4.4mm, Pitch 0.65mm, IPC Medium Density)
footprint 8A2_L (TSOP, 8-Leads, Body 3x4.4mm, Pitch 0.65mm, IPC High Density)
footprint 8A2_M (TSOP, 8-Leads, Body 3x4.4mm, Pitch 0.65mm, IPC Low Density)
pins: 1 GND (power), 2 NC, 3 SDA (io), 4 NC, 5 NC, 6 CLK (in), 7 NC, 8 VCC (power)

## AT88SC0104CA-Y6H-T
designator U?
AT88SC0104CA CryptoMemory®: 1-Kbit User Memory with Authentication and Encryption, Industrial (-40 to 85 degC), 8-Pad Mini-MAP Pkg, Pb-Free
footprint 8Y6_N (SON, 8-Leads, Body 2x3 mm, Pitch 0.5mm, IPC Medium Density)
footprint 8Y6_L (SON, 8-Leads, Body 2x3 mm, Pitch 0.5mm, IPC High Density)
footprint 8Y6_M (SON, 8-Leads, Body 2x3 mm, Pitch 0.5mm, IPC Low Density)
pins: 1 NC, 2 CLK (in), 3 NC, 4 VCC (power), 5 GND (power), 6 NC, 7 SDA (io), 8 NC, 9 Thermal Pad (power)

## AT88SC0204C-PU
designator U?
AT88SC0204C CryptoMemory®: 2-Kbit User Memory with Authentication and Encryption, Industrial (-40 to 85 degC), 8-Pin PDIP Pkg, Pb-Free
footprint 8P3 (DIP, 8-Leads, Row Spacing 7.62mm, Pitch 2.54mm, Body 9.59x6.61mm)
pins: 1 NC, 2 NC, 3 NC, 4 GND (power), 5 SDA (io), 6 SCL (in), 7 NC, 8 VCC (power)

## AT88SC0204C-SU
designator U?
AT88SC0204C CryptoMemory®: 2-Kbit User Memory with Authentication and Encryption, Industrial (-40 to 85 degC), 8-Pin SOIC Pkg, Pb-Free
footprint 8S1_N (SOIC, 8-Leads, Body 4.9x3.9mm, Pitch 1.27mm, IPC Medium Density)
footprint 8S1_L (SOIC, 8-Leads, Body 4.9x3.9mm, Pitch 1.27mm, IPC High Density)
footprint 8S1_M (SOIC, 8-Leads, Body 4.9x3.9mm, Pitch 1.27mm, IPC Low Density)
pins: 1 NC, 2 NC, 3 NC, 4 GND (power), 5 SDA (io), 6 SCL (in), 7 NC, 8 VCC (power)

## AT88SC0204CA-PU
designator U?
AT88SC0204CA CryptoMemory®: 2-Kbit User Memory with Authentication and Encryption, Industrial (-40 to 85 degC), 8-Pin PDIP Pkg, Pb-Free
footprint 8P3 (DIP, 8-Leads, Row Spacing 7.62mm, Pitch 2.54mm, Body 9.59x6.61mm)
pins: 1 NC, 2 NC, 3 NC, 4 GND (power), 5 SDA (io), 6 SCL (in), 7 NC, 8 VCC (power)

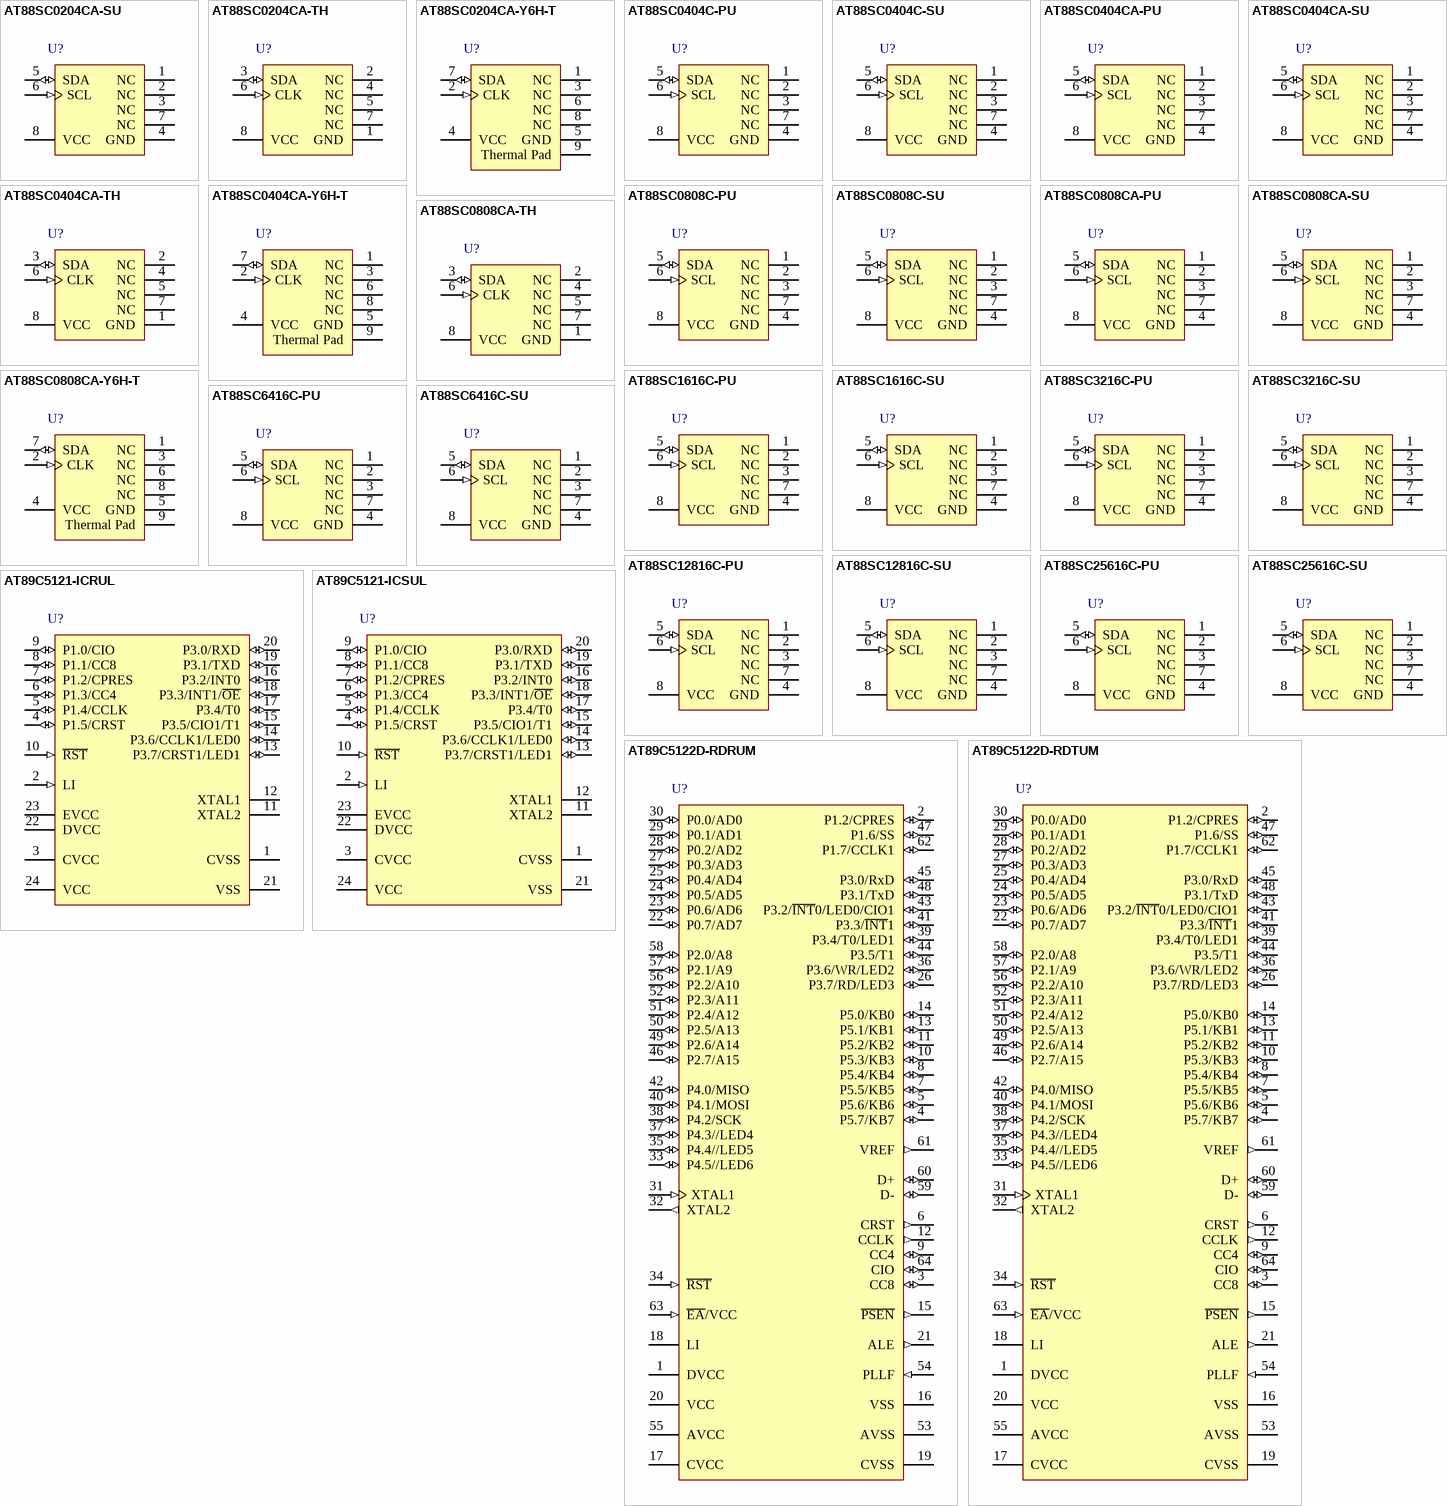
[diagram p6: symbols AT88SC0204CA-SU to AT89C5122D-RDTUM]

## AT88SC0204CA-SU
designator U?
AT88SC0204CA CryptoMemory®: 2-Kbit User Memory with Authentication and Encryption, Industrial (-40 to 85 degC), 8-Pin SOIC Pkg, Pb-Free
footprint 8S1_N (SOIC, 8-Leads, Body 4.9x3.9mm, Pitch 1.27mm, IPC Medium Density)
footprint 8S1_L (SOIC, 8-Leads, Body 4.9x3.9mm, Pitch 1.27mm, IPC High Density)
footprint 8S1_M (SOIC, 8-Leads, Body 4.9x3.9mm, Pitch 1.27mm, IPC Low Density)
pins: 1 NC, 2 NC, 3 NC, 4 GND (power), 5 SDA (io), 6 SCL (in), 7 NC, 8 VCC (power)

## AT88SC0204CA-TH
designator U?
AT88SC0204CA CryptoMemory®: 2-Kbit User Memory with Authentication and Encryption, Industrial (-40 to 85 degC), 8-Pin TSSOP Pkg, Pb-Free
footprint 8A2_N (TSOP, 8-Leads, Body 3x4.4mm, Pitch 0.65mm, IPC Medium Density)
footprint 8A2_L (TSOP, 8-Leads, Body 3x4.4mm, Pitch 0.65mm, IPC High Density)
footprint 8A2_M (TSOP, 8-Leads, Body 3x4.4mm, Pitch 0.65mm, IPC Low Density)
pins: 1 GND (power), 2 NC, 3 SDA (io), 4 NC, 5 NC, 6 CLK (in), 7 NC, 8 VCC (power)

## AT88SC0204CA-Y6H-T
designator U?
AT88SC0204CA CryptoMemory®: 2-Kbit User Memory with Authentication and Encryption, Industrial (-40 to 85 degC), 8-Pad Mini-MAP Pkg, Pb-Free
footprint 8Y6_N (SON, 8-Leads, Body 2x3 mm, Pitch 0.5mm, IPC Medium Density)
footprint 8Y6_L (SON, 8-Leads, Body 2x3 mm, Pitch 0.5mm, IPC High Density)
footprint 8Y6_M (SON, 8-Leads, Body 2x3 mm, Pitch 0.5mm, IPC Low Density)
pins: 1 NC, 2 CLK (in), 3 NC, 4 VCC (power), 5 GND (power), 6 NC, 7 SDA (io), 8 NC, 9 Thermal Pad (power)

## AT88SC0404C-PU
designator U?
AT88SC0404C CryptoMemory®: 4-Kbit User Memory with Authentication and Encryption, Industrial (-40 to 85 degC), 8-Pin PDIP Pkg, Pb-Free
footprint 8P3 (DIP, 8-Leads, Row Spacing 7.62mm, Pitch 2.54mm, Body 9.59x6.61mm)
pins: 1 NC, 2 NC, 3 NC, 4 GND (power), 5 SDA (io), 6 SCL (in), 7 NC, 8 VCC (power)

## AT88SC0404C-SU
designator U?
AT88SC0404C CryptoMemory®: 4-Kbit User Memory with Authentication and Encryption, Industrial (-40 to 85 degC), 8-Pin SOIC Pkg, Pb-Free
footprint 8S1_N (SOIC, 8-Leads, Body 4.9x3.9mm, Pitch 1.27mm, IPC Medium Density)
footprint 8S1_L (SOIC, 8-Leads, Body 4.9x3.9mm, Pitch 1.27mm, IPC High Density)
footprint 8S1_M (SOIC, 8-Leads, Body 4.9x3.9mm, Pitch 1.27mm, IPC Low Density)
pins: 1 NC, 2 NC, 3 NC, 4 GND (power), 5 SDA (io), 6 SCL (in), 7 NC, 8 VCC (power)

## AT88SC0404CA-PU
designator U?
AT88SC0404CA CryptoMemory®: 4-Kbit User Memory with Authentication and Encryption, Industrial (-40 to 85 degC), 8-Pin PDIP Pkg, Pb-Free
footprint 8P3 (DIP, 8-Leads, Row Spacing 7.62mm, Pitch 2.54mm, Body 9.59x6.61mm)
pins: 1 NC, 2 NC, 3 NC, 4 GND (power), 5 SDA (io), 6 SCL (in), 7 NC, 8 VCC (power)

## AT88SC0404CA-SU
designator U?
AT88SC0404CA CryptoMemory®: 4-Kbit User Memory with Authentication and Encryption, Industrial (-40 to 85 degC), 8-Pin SOIC Pkg, Pb-Free
footprint 8S1_N (SOIC, 8-Leads, Body 4.9x3.9mm, Pitch 1.27mm, IPC Medium Density)
footprint 8S1_L (SOIC, 8-Leads, Body 4.9x3.9mm, Pitch 1.27mm, IPC High Density)
footprint 8S1_M (SOIC, 8-Leads, Body 4.9x3.9mm, Pitch 1.27mm, IPC Low Density)
pins: 1 NC, 2 NC, 3 NC, 4 GND (power), 5 SDA (io), 6 SCL (in), 7 NC, 8 VCC (power)

## AT88SC0404CA-TH
designator U?
AT88SC0404CA CryptoMemory®: 4-Kbit User Memory with Authentication and Encryption, Industrial (-40 to 85 degC), 8-Pin TSSOP Pkg, Pb-Free
footprint 8A2_N (TSOP, 8-Leads, Body 3x4.4mm, Pitch 0.65mm, IPC Medium Density)
footprint 8A2_L (TSOP, 8-Leads, Body 3x4.4mm, Pitch 0.65mm, IPC High Density)
footprint 8A2_M (TSOP, 8-Leads, Body 3x4.4mm, Pitch 0.65mm, IPC Low Density)
pins: 1 GND (power), 2 NC, 3 SDA (io), 4 NC, 5 NC, 6 CLK (in), 7 NC, 8 VCC (power)

## AT88SC0404CA-Y6H-T
designator U?
AT88SC0404CA CryptoMemory®: 4-Kbit User Memory with Authentication and Encryption, Industrial (-40 to 85 degC), 8-Pad Mini-MAP Pkg, Pb-Free
footprint 8Y6_N (SON, 8-Leads, Body 2x3 mm, Pitch 0.5mm, IPC Medium Density)
footprint 8Y6_L (SON, 8-Leads, Body 2x3 mm, Pitch 0.5mm, IPC High Density)
footprint 8Y6_M (SON, 8-Leads, Body 2x3 mm, Pitch 0.5mm, IPC Low Density)
pins: 1 NC, 2 CLK (in), 3 NC, 4 VCC (power), 5 GND (power), 6 NC, 7 SDA (io), 8 NC, 9 Thermal Pad (power)

## AT88SC0808C-PU
designator U?
AT88SC0808C CryptoMemory®: 8-Kbit User Memory with Authentication and Encryption, Industrial (-40 to 85 degC), 8-Pin PDIP Pkg, Pb-Free
footprint 8P3 (DIP, 8-Leads, Row Spacing 7.62mm, Pitch 2.54mm, Body 9.59x6.61mm)
pins: 1 NC, 2 NC, 3 NC, 4 GND (power), 5 SDA (io), 6 SCL (in), 7 NC, 8 VCC (power)

## AT88SC0808C-SU
designator U?
AT88SC0808C CryptoMemory®: 8-Kbit User Memory with Authentication and Encryption, Industrial (-40 to 85 degC), 8-Pin SOIC Pkg, Pb-Free
footprint 8S1_N (SOIC, 8-Leads, Body 4.9x3.9mm, Pitch 1.27mm, IPC Medium Density)
footprint 8S1_L (SOIC, 8-Leads, Body 4.9x3.9mm, Pitch 1.27mm, IPC High Density)
footprint 8S1_M (SOIC, 8-Leads, Body 4.9x3.9mm, Pitch 1.27mm, IPC Low Density)
pins: 1 NC, 2 NC, 3 NC, 4 GND (power), 5 SDA (io), 6 SCL (in), 7 NC, 8 VCC (power)

## AT88SC0808CA-PU
designator U?
AT88SC0808CA CryptoMemory®: 8-Kbit User Memory with Authentication and Encryption, Industrial (-40 to 85 degC), 8-Pin PDIP Pkg, Pb-Free
footprint 8P3 (DIP, 8-Leads, Row Spacing 7.62mm, Pitch 2.54mm, Body 9.59x6.61mm)
pins: 1 NC, 2 NC, 3 NC, 4 GND (power), 5 SDA (io), 6 SCL (in), 7 NC, 8 VCC (power)

## AT88SC0808CA-SU
designator U?
AT88SC0808CA CryptoMemory®: 8-Kbit User Memory with Authentication and Encryption, Industrial (-40 to 85 degC), 8-Pin SOIC Pkg, Pb-Free
footprint 8S1_N (SOIC, 8-Leads, Body 4.9x3.9mm, Pitch 1.27mm, IPC Medium Density)
footprint 8S1_L (SOIC, 8-Leads, Body 4.9x3.9mm, Pitch 1.27mm, IPC High Density)
footprint 8S1_M (SOIC, 8-Leads, Body 4.9x3.9mm, Pitch 1.27mm, IPC Low Density)
pins: 1 NC, 2 NC, 3 NC, 4 GND (power), 5 SDA (io), 6 SCL (in), 7 NC, 8 VCC (power)

## AT88SC0808CA-TH
designator U?
AT88SC0808CA CryptoMemory®: 8-Kbit User Memory with Authentication and Encryption, Industrial (-40 to 85 degC), 8-Pin TSSOP Pkg, Pb-Free
footprint 8A2_N (TSOP, 8-Leads, Body 3x4.4mm, Pitch 0.65mm, IPC Medium Density)
footprint 8A2_L (TSOP, 8-Leads, Body 3x4.4mm, Pitch 0.65mm, IPC High Density)
footprint 8A2_M (TSOP, 8-Leads, Body 3x4.4mm, Pitch 0.65mm, IPC Low Density)
pins: 1 GND (power), 2 NC, 3 SDA (io), 4 NC, 5 NC, 6 CLK (in), 7 NC, 8 VCC (power)

## AT88SC0808CA-Y6H-T
designator U?
AT88SC0808CA CryptoMemory®: 8-Kbit User Memory with Authentication and Encryption, Industrial (-40 to 85 degC), 8-Pad Mini-MAP Pkg, Pb-Free
footprint 8Y6_N (SON, 8-Leads, Body 2x3 mm, Pitch 0.5mm, IPC Medium Density)
footprint 8Y6_L (SON, 8-Leads, Body 2x3 mm, Pitch 0.5mm, IPC High Density)
footprint 8Y6_M (SON, 8-Leads, Body 2x3 mm, Pitch 0.5mm, IPC Low Density)
pins: 1 NC, 2 CLK (in), 3 NC, 4 VCC (power), 5 GND (power), 6 NC, 7 SDA (io), 8 NC, 9 Thermal Pad (power)

## AT88SC1616C-PU
designator U?
AT88SC1616C CryptoMemory®: 16-Kbit User Memory with Authentication and Encryption, Industrial (-40 to 85 degC), 8-Pin PDIP Pkg, Pb-Free
footprint 8P3 (DIP, 8-Leads, Row Spacing 7.62mm, Pitch 2.54mm, Body 9.59x6.61mm)
pins: 1 NC, 2 NC, 3 NC, 4 GND (power), 5 SDA (io), 6 SCL (in), 7 NC, 8 VCC (power)

## AT88SC1616C-SU
designator U?
AT88SC1616C CryptoMemory®: 16-Kbit User Memory with Authentication and Encryption, Industrial (-40 to 85 degC), 8-Pin SOIC Pkg, Pb-Free
footprint 8S1_N (SOIC, 8-Leads, Body 4.9x3.9mm, Pitch 1.27mm, IPC Medium Density)
footprint 8S1_L (SOIC, 8-Leads, Body 4.9x3.9mm, Pitch 1.27mm, IPC High Density)
footprint 8S1_M (SOIC, 8-Leads, Body 4.9x3.9mm, Pitch 1.27mm, IPC Low Density)
pins: 1 NC, 2 NC, 3 NC, 4 GND (power), 5 SDA (io), 6 SCL (in), 7 NC, 8 VCC (power)

## AT88SC3216C-PU
designator U?
AT88SC3216C CryptoMemory®: 32-Kbit User Memory with Authentication and Encryption, Industrial (-40 to 85 degC), 8-Pin PDIP Pkg, Pb-Free
footprint 8P3 (DIP, 8-Leads, Row Spacing 7.62mm, Pitch 2.54mm, Body 9.59x6.61mm)
pins: 1 NC, 2 NC, 3 NC, 4 GND (power), 5 SDA (io), 6 SCL (in), 7 NC, 8 VCC (power)

## AT88SC3216C-SU
designator U?
AT88SC3216C CryptoMemory®: 32-Kbit User Memory with Authentication and Encryption, Industrial (-40 to 85 degC), 8-Pin SOIC Pkg, Pb-Free
footprint 8S1_N (SOIC, 8-Leads, Body 4.9x3.9mm, Pitch 1.27mm, IPC Medium Density)
footprint 8S1_L (SOIC, 8-Leads, Body 4.9x3.9mm, Pitch 1.27mm, IPC High Density)
footprint 8S1_M (SOIC, 8-Leads, Body 4.9x3.9mm, Pitch 1.27mm, IPC Low Density)
pins: 1 NC, 2 NC, 3 NC, 4 GND (power), 5 SDA (io), 6 SCL (in), 7 NC, 8 VCC (power)

## AT88SC6416C-PU
designator U?
AT88SC6416C CryptoMemory®: 64-Kbit User Memory with Authentication and Encryption, Industrial (-40 to 85 degC), 8-Pin PDIP Pkg, Pb-Free
footprint 8P3 (DIP, 8-Leads, Row Spacing 7.62mm, Pitch 2.54mm, Body 9.59x6.61mm)
pins: 1 NC, 2 NC, 3 NC, 4 GND (power), 5 SDA (io), 6 SCL (in), 7 NC, 8 VCC (power)

## AT88SC6416C-SU
designator U?
AT88SC6416C CryptoMemory®: 64-Kbit User Memory with Authentication and Encryption, Industrial (-40 to 85 degC), 8-Pin SOIC Pkg, Pb-Free
footprint 8S1_N (SOIC, 8-Leads, Body 4.9x3.9mm, Pitch 1.27mm, IPC Medium Density)
footprint 8S1_L (SOIC, 8-Leads, Body 4.9x3.9mm, Pitch 1.27mm, IPC High Density)
footprint 8S1_M (SOIC, 8-Leads, Body 4.9x3.9mm, Pitch 1.27mm, IPC Low Density)
pins: 1 NC, 2 NC, 3 NC, 4 GND (power), 5 SDA (io), 6 SCL (in), 7 NC, 8 VCC (power)

## AT88SC12816C-PU
designator U?
AT88SC12816C CryptoMemory®: 128-Kbit User Memory with Authentication and Encryption, Industrial (-40 to 85 degC), 8-Pin PDIP Pkg, Pb-Free
footprint 8P3 (DIP, 8-Leads, Row Spacing 7.62mm, Pitch 2.54mm, Body 9.59x6.61mm)
pins: 1 NC, 2 NC, 3 NC, 4 GND (power), 5 SDA (io), 6 SCL (in), 7 NC, 8 VCC (power)

## AT88SC12816C-SU
designator U?
AT88SC12816C CryptoMemory®: 128-Kbit User Memory with Authentication and Encryption, Industrial (-40 to 85 degC), 8-Pin SOIC Pkg, Pb-Free
footprint 8S1_N (SOIC, 8-Leads, Body 4.9x3.9mm, Pitch 1.27mm, IPC Medium Density)
footprint 8S1_L (SOIC, 8-Leads, Body 4.9x3.9mm, Pitch 1.27mm, IPC High Density)
footprint 8S1_M (SOIC, 8-Leads, Body 4.9x3.9mm, Pitch 1.27mm, IPC Low Density)
pins: 1 NC, 2 NC, 3 NC, 4 GND (power), 5 SDA (io), 6 SCL (in), 7 NC, 8 VCC (power)

## AT88SC25616C-PU
designator U?
AT88SC25616C CryptoMemory®: 256-Kbit User Memory with Authentication and Encryption, Industrial (-40 to 85 degC), 8-Pin PDIP Pkg, Pb-Free
footprint 8P3 (DIP, 8-Leads, Row Spacing 7.62mm, Pitch 2.54mm, Body 9.59x6.61mm)
pins: 1 NC, 2 NC, 3 NC, 4 GND (power), 5 SDA (io), 6 SCL (in), 7 NC, 8 VCC (power)

## AT88SC25616C-SU
designator U?
AT88SC25616C CryptoMemory®: 256-Kbit User Memory with Authentication and Encryption, Industrial (-40 to 85 degC), 8-Pin SOIC Pkg, Pb-Free
footprint 8S1_N (SOIC, 8-Leads, Body 4.9x3.9mm, Pitch 1.27mm, IPC Medium Density)
footprint 8S1_L (SOIC, 8-Leads, Body 4.9x3.9mm, Pitch 1.27mm, IPC High Density)
footprint 8S1_M (SOIC, 8-Leads, Body 4.9x3.9mm, Pitch 1.27mm, IPC Low Density)
pins: 1 NC, 2 NC, 3 NC, 4 GND (power), 5 SDA (io), 6 SCL (in), 7 NC, 8 VCC (power)

## AT89C5121-ICRUL
designator U?
8-bit Microcontroller with Multiprotocol Smart Card Interface, Industrial, 24-Pin SOIC Pkg, Tape and Reel, Pb-Free
footprint SSOP24_N (SOP, 24-Leads, Body 8.2x5.3mm, Pitch 0.65mm, IPC Medium Density)
footprint SSOP24_L (SOP, 24-Leads, Body 8.2x5.3mm, Pitch 0.65mm, IPC High Density)
footprint SSOP24_M (SOP, 24-Leads, Body 8.2x5.3mm, Pitch 0.65mm, IPC Low Density)
pins: 1 CVSS (power), 2 LI (in), 3 CVCC (power), 4 P1.5/CRST (io), 5 P1.4/CCLK (io), 6 P1.3/CC4 (io), 7 P1.2/CPRES (io), 8 P1.1/CC8 (io), 9 P1.0/CIO (io), 10 ~{RST} (in), 11 XTAL2, 12 XTAL1, 13 P3.7/CRST1/LED1 (io), 14 P3.6/CCLK1/LED0 (io), 15 P3.5/CIO1/T1 (io), 16 P3.2/INT0 (io), 17 P3.4/T0 (io), 18 P3.3/INT1/~{OE} (io), 19 P3.1/TXD (io), 20 P3.0/RXD (io), 21 VSS (power), 22 DVCC (power), 23 EVCC (power), 24 VCC (power)

## AT89C5121-ICSUL
designator U?
8-bit Microcontroller with Multiprotocol Smart Card Interface, Industrial, 24-Pin SOIC Pkg, Stick, Pb-Free
footprint SSOP24_N (SOP, 24-Leads, Body 8.2x5.3mm, Pitch 0.65mm, IPC Medium Density)
footprint SSOP24_L (SOP, 24-Leads, Body 8.2x5.3mm, Pitch 0.65mm, IPC High Density)
footprint SSOP24_M (SOP, 24-Leads, Body 8.2x5.3mm, Pitch 0.65mm, IPC Low Density)
pins: 1 CVSS (power), 2 LI (in), 3 CVCC (power), 4 P1.5/CRST (io), 5 P1.4/CCLK (io), 6 P1.3/CC4 (io), 7 P1.2/CPRES (io), 8 P1.1/CC8 (io), 9 P1.0/CIO (io), 10 ~{RST} (in), 11 XTAL2, 12 XTAL1, 13 P3.7/CRST1/LED1 (io), 14 P3.6/CCLK1/LED0 (io), 15 P3.5/CIO1/T1 (io), 16 P3.2/INT0 (io), 17 P3.4/T0 (io), 18 P3.3/INT1/~{OE} (io), 19 P3.1/TXD (io), 20 P3.0/RXD (io), 21 VSS (power), 22 DVCC (power), 23 EVCC (power), 24 VCC (power)

## AT89C5122D-RDRUM
designator U?
C51 Microcontroller with USB and Smart Card Reader Interfaces, 32K FLASH, Industrial, 64-Pin QFP Pkg, Tape and Reel and Dry Pack
footprint LQFP64_N (Thin QFP, 64-Leads, Body 10x10mm, Pitch 0.5mm, IPC Medium Density)
footprint LQFP64_L (Thin QFP, 64-Leads, Body 10x10mm, Pitch 0.5mm, IPC High Density)
footprint LQFP64_M (Thin QFP, 64-Leads, Body 10x10mm, Pitch 0.5mm, IPC Low Density)
pins: 1 DVCC (power), 2 P1.2/CPRES (io), 3 CC8 (io), 4 P5.7/KB7 (io), 5 P5.6/KB6 (io), 6 CRST (out), 7 P5.5/KB5 (io), 8 P5.4/KB4 (io), 9 CC4 (io), 10 P5.3/KB3 (io), 11 P5.2/KB2 (io), 12 CCLK (out), 13 P5.1/KB1 (io), 14 P5.0/KB0 (io), 15 ~{PSEN} (out), 16 VSS (power), 17 CVCC (power), 18 LI (power), 19 CVSS (power), 20 VCC (power), 21 ALE (out), 22 P0.7/AD7 (io), 23 P0.6/AD6 (io), 24 P0.5/AD5 (io), 25 P0.4/AD4 (io), 26 P3.7/RD/LED3 (io), 27 P0.3/AD3 (io), 28 P0.2/AD2 (io), 29 P0.1/AD1 (io), 30 P0.0/AD0 (io), 31 XTAL1 (in), 32 XTAL2 (out), 33 P4.5//LED6 (io), 34 ~{RST} (in), 35 P4.4//LED5 (io), 36 P3.6/WR/LED2 (io), 37 P4.3//LED4 (io), 38 P4.2/SCK (io), 39 P3.4/T0/LED1 (io), 40 P4.1/MOSI (io), 41 P3.3/~{INT}1 (io), 42 P4.0/MISO (io), 43 P3.2/~{INT}0/LED0/CIO1 (io), 44 P3.5/T1 (io), 45 P3.0/RxD (io), 46 P2.7/A15 (io), 47 P1.6/SS (io), 48 P3.1/TxD (io), 49 P2.6/A14 (io), 50 P2.5/A13 (io), 51 P2.4/A12 (io), 52 P2.3/A11 (io), 53 AVSS (power), 54 PLLF (in), 55 AVCC (power), 56 P2.2/A10 (io), 57 P2.1/A9 (io), 58 P2.0/A8 (io), 59 D- (io), 60 D+ (io), 61 VREF (out), 62 P1.7/CCLK1 (io), 63 ~{EA}/VCC (in), 64 CIO (io)

## AT89C5122D-RDTUM
designator U?
C51 Microcontroller with USB and Smart Card Reader Interfaces, 32K FLASH, Industrial, 64-Pin QFP Pkg, Tray and Dry Pack
footprint LQFP64_N (Thin QFP, 64-Leads, Body 10x10mm, Pitch 0.5mm, IPC Medium Density)
footprint LQFP64_L (Thin QFP, 64-Leads, Body 10x10mm, Pitch 0.5mm, IPC High Density)
footprint LQFP64_M (Thin QFP, 64-Leads, Body 10x10mm, Pitch 0.5mm, IPC Low Density)
pins: 1 DVCC (power), 2 P1.2/CPRES (io), 3 CC8 (io), 4 P5.7/KB7 (io), 5 P5.6/KB6 (io), 6 CRST (out), 7 P5.5/KB5 (io), 8 P5.4/KB4 (io), 9 CC4 (io), 10 P5.3/KB3 (io), 11 P5.2/KB2 (io), 12 CCLK (out), 13 P5.1/KB1 (io), 14 P5.0/KB0 (io), 15 ~{PSEN} (out), 16 VSS (power), 17 CVCC (power), 18 LI (power), 19 CVSS (power), 20 VCC (power), 21 ALE (out), 22 P0.7/AD7 (io), 23 P0.6/AD6 (io), 24 P0.5/AD5 (io), 25 P0.4/AD4 (io), 26 P3.7/RD/LED3 (io), 27 P0.3/AD3 (io), 28 P0.2/AD2 (io), 29 P0.1/AD1 (io), 30 P0.0/AD0 (io), 31 XTAL1 (in), 32 XTAL2 (out), 33 P4.5//LED6 (io), 34 ~{RST} (in), 35 P4.4//LED5 (io), 36 P3.6/WR/LED2 (io), 37 P4.3//LED4 (io), 38 P4.2/SCK (io), 39 P3.4/T0/LED1 (io), 40 P4.1/MOSI (io), 41 P3.3/~{INT}1 (io), 42 P4.0/MISO (io), 43 P3.2/~{INT}0/LED0/CIO1 (io), 44 P3.5/T1 (io), 45 P3.0/RxD (io), 46 P2.7/A15 (io), 47 P1.6/SS (io), 48 P3.1/TxD (io), 49 P2.6/A14 (io), 50 P2.5/A13 (io), 51 P2.4/A12 (io), 52 P2.3/A11 (io), 53 AVSS (power), 54 PLLF (in), 55 AVCC (power), 56 P2.2/A10 (io), 57 P2.1/A9 (io), 58 P2.0/A8 (io), 59 D- (io), 60 D+ (io), 61 VREF (out), 62 P1.7/CCLK1 (io), 63 ~{EA}/VCC (in), 64 CIO (io)

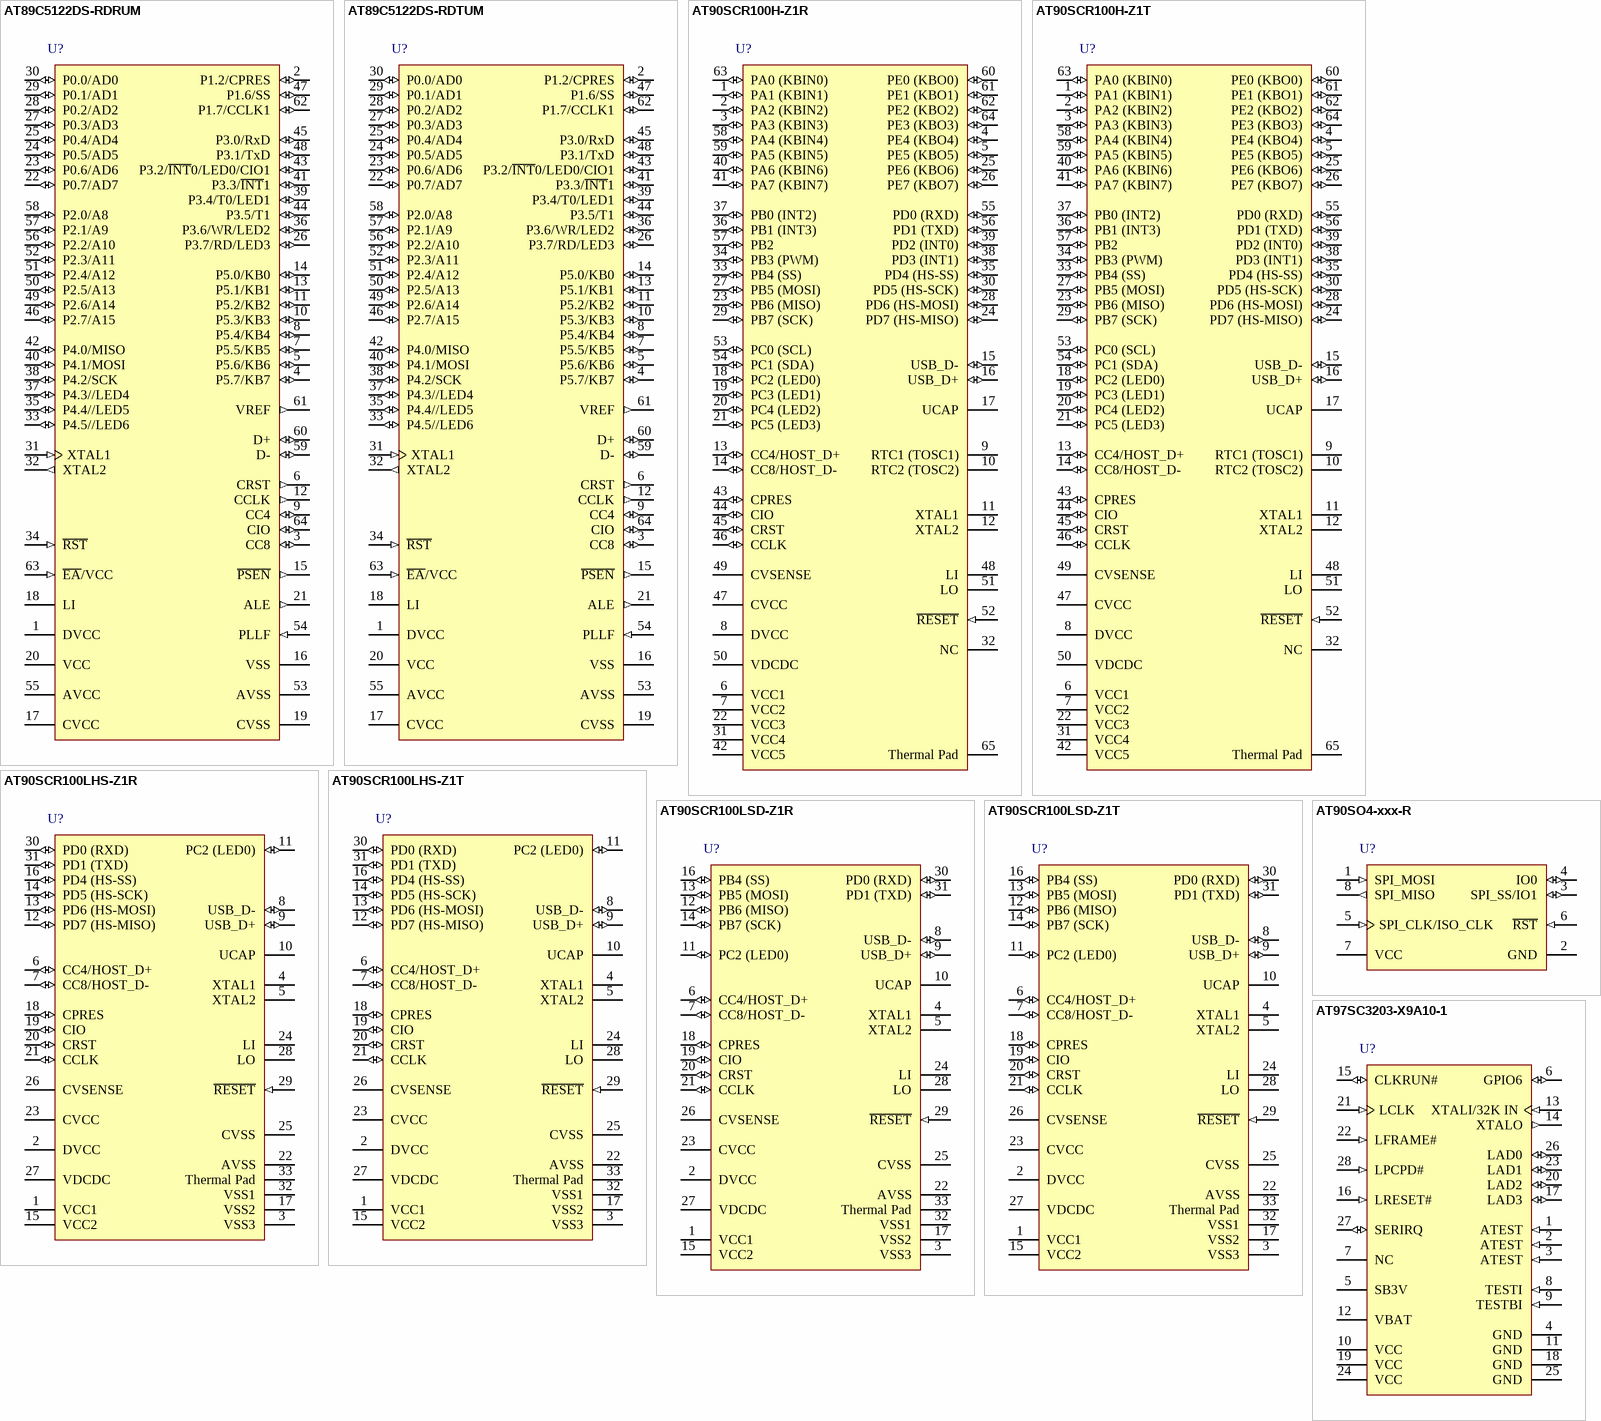
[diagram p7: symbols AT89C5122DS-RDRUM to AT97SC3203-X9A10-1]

## AT89C5122DS-RDRUM
designator U?
C51 Microcontroller with USB and Smart Card Reader Interfaces, 32K FLASH, Industrial, 64-Pin QFP Pkg, Tape and Reel and Dry Pack
footprint LQFP64_N (Thin QFP, 64-Leads, Body 10x10mm, Pitch 0.5mm, IPC Medium Density)
footprint LQFP64_L (Thin QFP, 64-Leads, Body 10x10mm, Pitch 0.5mm, IPC High Density)
footprint LQFP64_M (Thin QFP, 64-Leads, Body 10x10mm, Pitch 0.5mm, IPC Low Density)
pins: 1 DVCC (power), 2 P1.2/CPRES (io), 3 CC8 (io), 4 P5.7/KB7 (io), 5 P5.6/KB6 (io), 6 CRST (out), 7 P5.5/KB5 (io), 8 P5.4/KB4 (io), 9 CC4 (io), 10 P5.3/KB3 (io), 11 P5.2/KB2 (io), 12 CCLK (out), 13 P5.1/KB1 (io), 14 P5.0/KB0 (io), 15 ~{PSEN} (out), 16 VSS (power), 17 CVCC (power), 18 LI (power), 19 CVSS (power), 20 VCC (power), 21 ALE (out), 22 P0.7/AD7 (io), 23 P0.6/AD6 (io), 24 P0.5/AD5 (io), 25 P0.4/AD4 (io), 26 P3.7/RD/LED3 (io), 27 P0.3/AD3 (io), 28 P0.2/AD2 (io), 29 P0.1/AD1 (io), 30 P0.0/AD0 (io), 31 XTAL1 (in), 32 XTAL2 (out), 33 P4.5//LED6 (io), 34 ~{RST} (in), 35 P4.4//LED5 (io), 36 P3.6/WR/LED2 (io), 37 P4.3//LED4 (io), 38 P4.2/SCK (io), 39 P3.4/T0/LED1 (io), 40 P4.1/MOSI (io), 41 P3.3/~{INT}1 (io), 42 P4.0/MISO (io), 43 P3.2/~{INT}0/LED0/CIO1 (io), 44 P3.5/T1 (io), 45 P3.0/RxD (io), 46 P2.7/A15 (io), 47 P1.6/SS (io), 48 P3.1/TxD (io), 49 P2.6/A14 (io), 50 P2.5/A13 (io), 51 P2.4/A12 (io), 52 P2.3/A11 (io), 53 AVSS (power), 54 PLLF (in), 55 AVCC (power), 56 P2.2/A10 (io), 57 P2.1/A9 (io), 58 P2.0/A8 (io), 59 D- (io), 60 D+ (io), 61 VREF (out), 62 P1.7/CCLK1 (io), 63 ~{EA}/VCC (in), 64 CIO (io)

## AT89C5122DS-RDTUM
designator U?
C51 Microcontroller with USB and Smart Card Reader Interfaces, 32K FLASH, Industrial, 64-Pin QFP Pkg, Tray and Dry Pack
footprint LQFP64_N (Thin QFP, 64-Leads, Body 10x10mm, Pitch 0.5mm, IPC Medium Density)
footprint LQFP64_L (Thin QFP, 64-Leads, Body 10x10mm, Pitch 0.5mm, IPC High Density)
footprint LQFP64_M (Thin QFP, 64-Leads, Body 10x10mm, Pitch 0.5mm, IPC Low Density)
pins: 1 DVCC (power), 2 P1.2/CPRES (io), 3 CC8 (io), 4 P5.7/KB7 (io), 5 P5.6/KB6 (io), 6 CRST (out), 7 P5.5/KB5 (io), 8 P5.4/KB4 (io), 9 CC4 (io), 10 P5.3/KB3 (io), 11 P5.2/KB2 (io), 12 CCLK (out), 13 P5.1/KB1 (io), 14 P5.0/KB0 (io), 15 ~{PSEN} (out), 16 VSS (power), 17 CVCC (power), 18 LI (power), 19 CVSS (power), 20 VCC (power), 21 ALE (out), 22 P0.7/AD7 (io), 23 P0.6/AD6 (io), 24 P0.5/AD5 (io), 25 P0.4/AD4 (io), 26 P3.7/RD/LED3 (io), 27 P0.3/AD3 (io), 28 P0.2/AD2 (io), 29 P0.1/AD1 (io), 30 P0.0/AD0 (io), 31 XTAL1 (in), 32 XTAL2 (out), 33 P4.5//LED6 (io), 34 ~{RST} (in), 35 P4.4//LED5 (io), 36 P3.6/WR/LED2 (io), 37 P4.3//LED4 (io), 38 P4.2/SCK (io), 39 P3.4/T0/LED1 (io), 40 P4.1/MOSI (io), 41 P3.3/~{INT}1 (io), 42 P4.0/MISO (io), 43 P3.2/~{INT}0/LED0/CIO1 (io), 44 P3.5/T1 (io), 45 P3.0/RxD (io), 46 P2.7/A15 (io), 47 P1.6/SS (io), 48 P3.1/TxD (io), 49 P2.6/A14 (io), 50 P2.5/A13 (io), 51 P2.4/A12 (io), 52 P2.3/A11 (io), 53 AVSS (power), 54 PLLF (in), 55 AVCC (power), 56 P2.2/A10 (io), 57 P2.1/A9 (io), 58 P2.0/A8 (io), 59 D- (io), 60 D+ (io), 61 VREF (out), 62 P1.7/CCLK1 (io), 63 ~{EA}/VCC (in), 64 CIO (io)

## AT90SCR100H-Z1R
designator U?
8-bit AVR® Microcontroller for Smart Card Readers, Industrial, 64-Pin QFN Pkg, Reel, Pb-Free
footprint QFN64_N (QFN, 64-Leads, Body 9x9mm, Pitch 0.5mm, IPC Medium Density)
footprint QFN64_L (QFN, 64-Leads, Body 9x9mm, Pitch 0.5mm, IPC High Density)
footprint QFN64_M (QFN, 64-Leads, Body 9x9mm, Pitch 0.5mm, IPC Low Density)
pins: 1 PA1 (KBIN1) (io), 2 PA2 (KBIN2) (io), 3 PA3 (KBIN3) (io), 4 PE4 (KBO4) (io), 5 PE5 (KBO5) (io), 6 VCC1 (power), 7 VCC2 (power), 8 DVCC (power), 9 RTC1 (TOSC1), 10 RTC2 (TOSC2), 11 XTAL1, 12 XTAL2, 13 CC4/HOST_D+ (io), 14 CC8/HOST_D- (io), 15 USB_D- (io), 16 USB_D+ (io), 17 UCAP, 18 PC2 (LED0) (io), 19 PC3 (LED1) (io), 20 PC4 (LED2) (io), 21 PC5 (LED3) (io), 22 VCC3 (power), 23 PB6 (MISO) (io), 24 PD7 (HS-MISO) (io), 25 PE6 (KBO6) (io), 26 PE7 (KBO7) (io), 27 PB5 (MOSI) (io), 28 PD6 (HS-MOSI) (io), 29 PB7 (SCK) (io), 30 PD5 (HS-SCK) (io), 31 VCC4 (power), 32 NC, 33 PB4 (SS) (io), 34 PB3 (PWM) (io), 35 PD4 (HS-SS) (io), 36 PB1 (INT3) (io), 37 PB0 (INT2) (io), 38 PD3 (INT1) (io), 39 PD2 (INT0) (io), 40 PA6 (KBIN6) (io), 41 PA7 (KBIN7) (io), 42 VCC5 (power), 43 CPRES (io), 44 CIO (io), 45 CRST (io), 46 CCLK (io), 47 CVCC (power), 48 LI, 49 CVSENSE, 50 VDCDC (power), 51 LO, 52 ~{RESET} (in), 53 PC0 (SCL) (io), 54 PC1 (SDA) (io), 55 PD0 (RXD) (io), 56 PD1 (TXD) (io), 57 PB2 (io), 58 PA4 (KBIN4) (io), 59 PA5 (KBIN5) (io), 60 PE0 (KBO0) (io), 61 PE1 (KBO1) (io), 62 PE2 (KBO2) (io), 63 PA0 (KBIN0) (io), 64 PE3 (KBO3) (io), 65 Thermal Pad (power)

## AT90SCR100H-Z1T
designator U?
8-bit AVR® Microcontroller for Smart Card Readers, Industrial, 64-Pin QFN Pkg, Tray, Pb-Free
footprint QFN64_N (QFN, 64-Leads, Body 9x9mm, Pitch 0.5mm, IPC Medium Density)
footprint QFN64_L (QFN, 64-Leads, Body 9x9mm, Pitch 0.5mm, IPC High Density)
footprint QFN64_M (QFN, 64-Leads, Body 9x9mm, Pitch 0.5mm, IPC Low Density)
pins: 1 PA1 (KBIN1) (io), 2 PA2 (KBIN2) (io), 3 PA3 (KBIN3) (io), 4 PE4 (KBO4) (io), 5 PE5 (KBO5) (io), 6 VCC1 (power), 7 VCC2 (power), 8 DVCC (power), 9 RTC1 (TOSC1), 10 RTC2 (TOSC2), 11 XTAL1, 12 XTAL2, 13 CC4/HOST_D+ (io), 14 CC8/HOST_D- (io), 15 USB_D- (io), 16 USB_D+ (io), 17 UCAP, 18 PC2 (LED0) (io), 19 PC3 (LED1) (io), 20 PC4 (LED2) (io), 21 PC5 (LED3) (io), 22 VCC3 (power), 23 PB6 (MISO) (io), 24 PD7 (HS-MISO) (io), 25 PE6 (KBO6) (io), 26 PE7 (KBO7) (io), 27 PB5 (MOSI) (io), 28 PD6 (HS-MOSI) (io), 29 PB7 (SCK) (io), 30 PD5 (HS-SCK) (io), 31 VCC4 (power), 32 NC, 33 PB4 (SS) (io), 34 PB3 (PWM) (io), 35 PD4 (HS-SS) (io), 36 PB1 (INT3) (io), 37 PB0 (INT2) (io), 38 PD3 (INT1) (io), 39 PD2 (INT0) (io), 40 PA6 (KBIN6) (io), 41 PA7 (KBIN7) (io), 42 VCC5 (power), 43 CPRES (io), 44 CIO (io), 45 CRST (io), 46 CCLK (io), 47 CVCC (power), 48 LI, 49 CVSENSE, 50 VDCDC (power), 51 LO, 52 ~{RESET} (in), 53 PC0 (SCL) (io), 54 PC1 (SDA) (io), 55 PD0 (RXD) (io), 56 PD1 (TXD) (io), 57 PB2 (io), 58 PA4 (KBIN4) (io), 59 PA5 (KBIN5) (io), 60 PE0 (KBO0) (io), 61 PE1 (KBO1) (io), 62 PE2 (KBO2) (io), 63 PA0 (KBIN0) (io), 64 PE3 (KBO3) (io), 65 Thermal Pad (power)

## AT90SCR100LHS-Z1R
designator U?
8-bit AVR® Microcontroller for Smart Card Readers, High-Speed SPI, Industrial, 32-Pin QFN Pkg, Reel, Pb-Free
footprint RQFN032_H_N (QFN, 32-Leads, Body 5x5mm, Pitch 0.5mm, IPC Medium Density)
footprint RQFN032_H_L (QFN, 32-Leads, Body 5x5mm, Pitch 0.5mm, IPC High Density)
footprint RQFN032_H_M (QFN, 32-Leads, Body 5x5mm, Pitch 0.5mm, IPC Low Density)
pins: 1 VCC1 (power), 2 DVCC (power), 3 VSS3 (power), 4 XTAL1, 5 XTAL2, 6 CC4/HOST_D+ (io), 7 CC8/HOST_D- (io), 8 USB_D- (io), 9 USB_D+ (io), 10 UCAP, 11 PC2 (LED0) (io), 12 PD7 (HS-MISO) (io), 13 PD6 (HS-MOSI) (io), 14 PD5 (HS-SCK) (io), 15 VCC2 (power), 16 PD4 (HS-SS) (io), 17 VSS2 (power), 18 CPRES (io), 19 CIO (io), 20 CRST (io), 21 CCLK (io), 22 AVSS (power), 23 CVCC (power), 24 LI, 25 CVSS (power), 26 CVSENSE, 27 VDCDC (power), 28 LO, 29 ~{RESET} (in), 30 PD0 (RXD) (io), 31 PD1 (TXD) (io), 32 VSS1 (power), 33 Thermal Pad (power)

## AT90SCR100LHS-Z1T
designator U?
8-bit AVR® Microcontroller for Smart Card Readers, High-Speed SPI, Industrial, 32-Pin QFN Pkg, Tray, Pb-Free
footprint RQFN032_H_N (QFN, 32-Leads, Body 5x5mm, Pitch 0.5mm, IPC Medium Density)
footprint RQFN032_H_L (QFN, 32-Leads, Body 5x5mm, Pitch 0.5mm, IPC High Density)
footprint RQFN032_H_M (QFN, 32-Leads, Body 5x5mm, Pitch 0.5mm, IPC Low Density)
pins: 1 VCC1 (power), 2 DVCC (power), 3 VSS3 (power), 4 XTAL1, 5 XTAL2, 6 CC4/HOST_D+ (io), 7 CC8/HOST_D- (io), 8 USB_D- (io), 9 USB_D+ (io), 10 UCAP, 11 PC2 (LED0) (io), 12 PD7 (HS-MISO) (io), 13 PD6 (HS-MOSI) (io), 14 PD5 (HS-SCK) (io), 15 VCC2 (power), 16 PD4 (HS-SS) (io), 17 VSS2 (power), 18 CPRES (io), 19 CIO (io), 20 CRST (io), 21 CCLK (io), 22 AVSS (power), 23 CVCC (power), 24 LI, 25 CVSS (power), 26 CVSENSE, 27 VDCDC (power), 28 LO, 29 ~{RESET} (in), 30 PD0 (RXD) (io), 31 PD1 (TXD) (io), 32 VSS1 (power), 33 Thermal Pad (power)

## AT90SCR100LSD-Z1R
designator U?
8-bit AVR® Microcontroller for Smart Card Readers, Standard SPI, Industrial, 32-Pin QFN Pkg, Reel, Pb-Free
footprint RQFN032_H_N (QFN, 32-Leads, Body 5x5mm, Pitch 0.5mm, IPC Medium Density)
footprint RQFN032_H_L (QFN, 32-Leads, Body 5x5mm, Pitch 0.5mm, IPC High Density)
footprint RQFN032_H_M (QFN, 32-Leads, Body 5x5mm, Pitch 0.5mm, IPC Low Density)
pins: 1 VCC1 (power), 2 DVCC (power), 3 VSS3 (power), 4 XTAL1, 5 XTAL2, 6 CC4/HOST_D+ (io), 7 CC8/HOST_D- (io), 8 USB_D- (io), 9 USB_D+ (io), 10 UCAP, 11 PC2 (LED0) (io), 12 PB6 (MISO) (io), 13 PB5 (MOSI) (io), 14 PB7 (SCK) (io), 15 VCC2 (power), 16 PB4 (SS) (io), 17 VSS2 (power), 18 CPRES (io), 19 CIO (io), 20 CRST (io), 21 CCLK (io), 22 AVSS (power), 23 CVCC (power), 24 LI, 25 CVSS (power), 26 CVSENSE, 27 VDCDC (power), 28 LO, 29 ~{RESET} (in), 30 PD0 (RXD) (io), 31 PD1 (TXD) (io), 32 VSS1 (power), 33 Thermal Pad (power)

## AT90SCR100LSD-Z1T
designator U?
8-bit AVR® Microcontroller for Smart Card Readers, Standard SPI, Industrial, 32-Pin QFN Pkg, Tray, Pb-Free
footprint RQFN032_H_N (QFN, 32-Leads, Body 5x5mm, Pitch 0.5mm, IPC Medium Density)
footprint RQFN032_H_L (QFN, 32-Leads, Body 5x5mm, Pitch 0.5mm, IPC High Density)
footprint RQFN032_H_M (QFN, 32-Leads, Body 5x5mm, Pitch 0.5mm, IPC Low Density)
pins: 1 VCC1 (power), 2 DVCC (power), 3 VSS3 (power), 4 XTAL1, 5 XTAL2, 6 CC4/HOST_D+ (io), 7 CC8/HOST_D- (io), 8 USB_D- (io), 9 USB_D+ (io), 10 UCAP, 11 PC2 (LED0) (io), 12 PB6 (MISO) (io), 13 PB5 (MOSI) (io), 14 PB7 (SCK) (io), 15 VCC2 (power), 16 PB4 (SS) (io), 17 VSS2 (power), 18 CPRES (io), 19 CIO (io), 20 CRST (io), 21 CCLK (io), 22 AVSS (power), 23 CVCC (power), 24 LI, 25 CVSS (power), 26 CVSENSE, 27 VDCDC (power), 28 LO, 29 ~{RESET} (in), 30 PD0 (RXD) (io), 31 PD1 (TXD) (io), 32 VSS1 (power), 33 Thermal Pad (power)

## AT90SO4-xxx-R
designator U?
Secure Microcontroller for Security Modules, 8-Pin SOIC Pkg
footprint T5_N (SOP, 8-Leads, Body 5.2x5.3mm, Pitch 1.27mm, IPC Medium Density)
footprint T5_L (SOP, 8-Leads, Body 5.2x5.3mm, Pitch 1.27mm, IPC High Density)
footprint T5_M (SOP, 8-Leads, Body 5.2x5.3mm, Pitch 1.27mm, IPC Low Density)
pins: 1 SPI_MOSI (in), 2 GND (power), 3 SPI_SS/IO1 (io), 4 IO0 (io), 5 SPI_CLK/ISO_CLK (in), 6 ~{RST} (in), 7 VCC (power), 8 SPI_MISO (out)

## AT97SC3203-X9A10-1
designator U?
Trusted Platform Module, Low Pin Count Interface, Commercial (0 to 70 deg C), 28-Pin TSSOP, Pb-Free
footprint 28A3_N (TSOP, 28-Leads, Body 9.7x6.1mm, Pitch 0.65mm, IPC Medium Density)
footprint 28A3_L (TSOP, 28-Leads, Body 9.7x6.1mm, Pitch 0.65mm, IPC High Density)
footprint 28A3_M (TSOP, 28-Leads, Body 9.7x6.1mm, Pitch 0.65mm, IPC Low Density)
pins: 1 ATEST (in), 2 ATEST (in), 3 ATEST (in), 4 GND (power), 5 SB3V (power), 6 GPIO6 (io), 7 NC, 8 TESTI (in), 9 TESTBI (in), 10 VCC (power), 11 GND (power), 12 VBAT (power), 13 XTALI/32K IN (in), 14 XTALO (out), 15 CLKRUN# (io), 16 LRESET# (in), 17 LAD3 (io), 18 GND (power), 19 VCC (power), 20 LAD2 (io), 21 LCLK (in), 22 LFRAME# (in), 23 LAD1 (io), 24 VCC (power), 25 GND (power), 26 LAD0 (io), 27 SERIRQ (io), 28 LPCPD# (in)

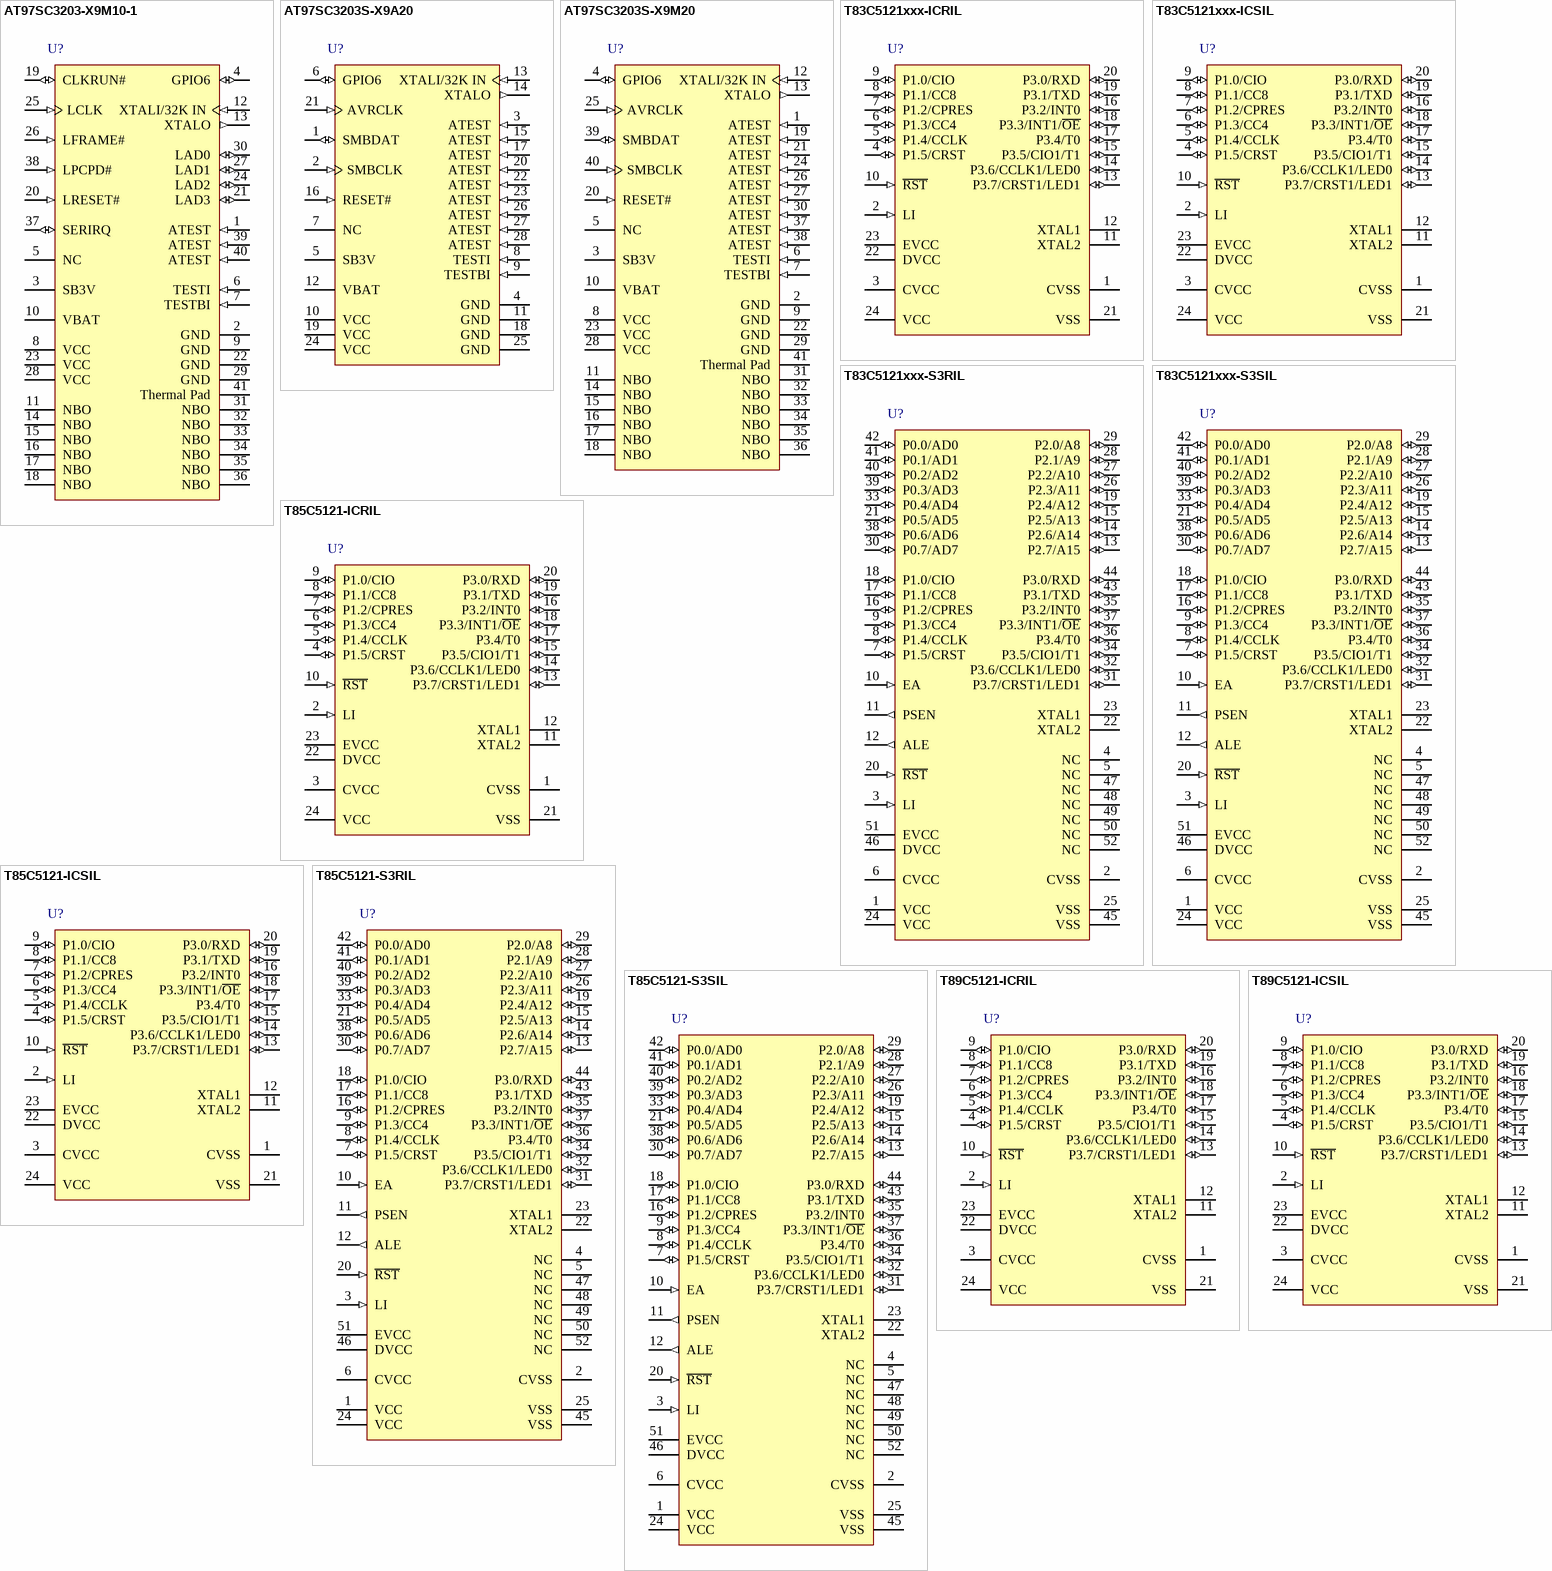
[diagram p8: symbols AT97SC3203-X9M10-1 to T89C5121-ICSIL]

## AT97SC3203-X9M10-1
designator U?
Trusted Platform Module, Low Pin Count Interface, Commercial (0 to 70 deg C), 40-Pin QFN, Pb-Free
footprint 40ML1_N (QFN, 40-Leads, Body 6x6mm, Pitch 0.5mm, IPC Medium Density)
footprint 40ML1_L (QFN, 40-Leads, Body 6x6mm, Pitch 0.5mm, IPC High Density)
footprint 40ML1_M (QFN, 40-Leads, Body 6x6mm, Pitch 0.5mm, IPC Low Density)
pins: 1 ATEST (in), 2 GND (power), 3 SB3V (power), 4 GPIO6 (io), 5 NC, 6 TESTI (in), 7 TESTBI (in), 8 VCC (power), 9 GND (power), 10 VBAT (power), 11 NBO, 12 XTALI/32K IN (in), 13 XTALO (out), 14 NBO, 15 NBO, 16 NBO, 17 NBO, 18 NBO, 19 CLKRUN# (io), 20 LRESET# (in), 21 LAD3 (io), 22 GND (power), 23 VCC (power), 24 LAD2 (io), 25 LCLK (in), 26 LFRAME# (in), 27 LAD1 (io), 28 VCC (power), 29 GND (power), 30 LAD0 (io), 31 NBO, 32 NBO, 33 NBO, 34 NBO, 35 NBO, 36 NBO, 37 SERIRQ (io), 38 LPCPD# (in), 39 ATEST (in), 40 ATEST (in), 41 Thermal Pad (power)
